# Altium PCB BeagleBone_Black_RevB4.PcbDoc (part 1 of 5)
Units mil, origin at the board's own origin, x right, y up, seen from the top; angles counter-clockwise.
Board outline 3401 x 2151 mil, 6 copper layers (TOP, LYR2_GND, LYR3, LYR4, LYR5_PWR, BOTTOM), stack 62 mil thick; 381 components, 310 nets, 1705 pads, 850 vias.
Unrouted connection lines stored in the file: 1.
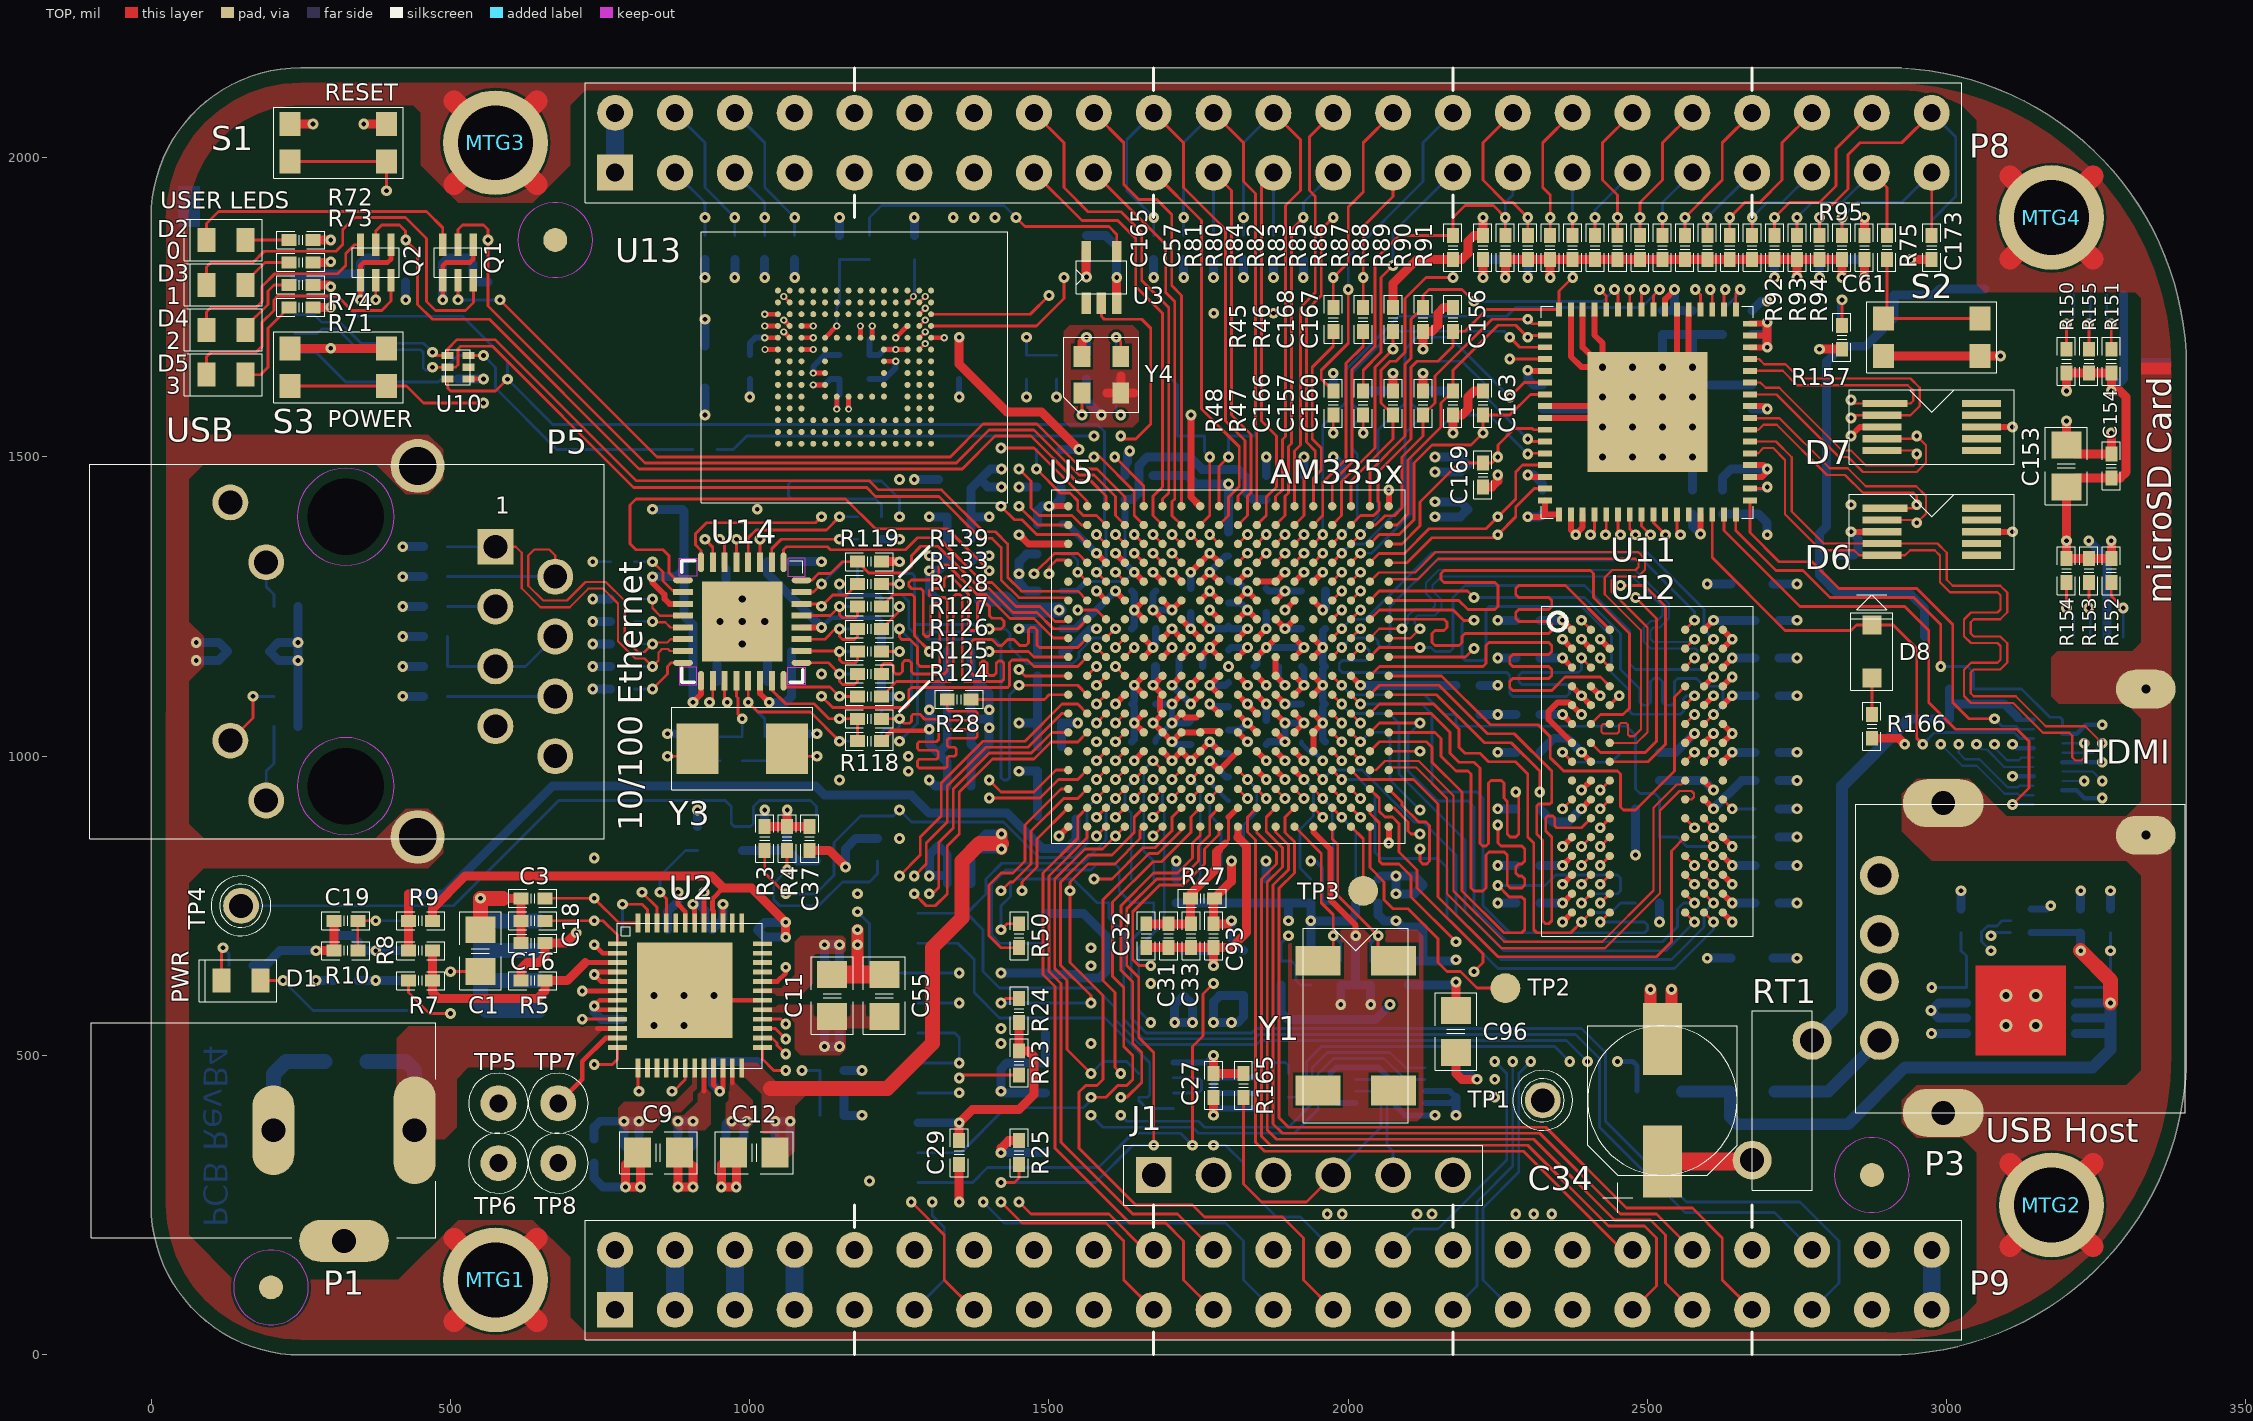
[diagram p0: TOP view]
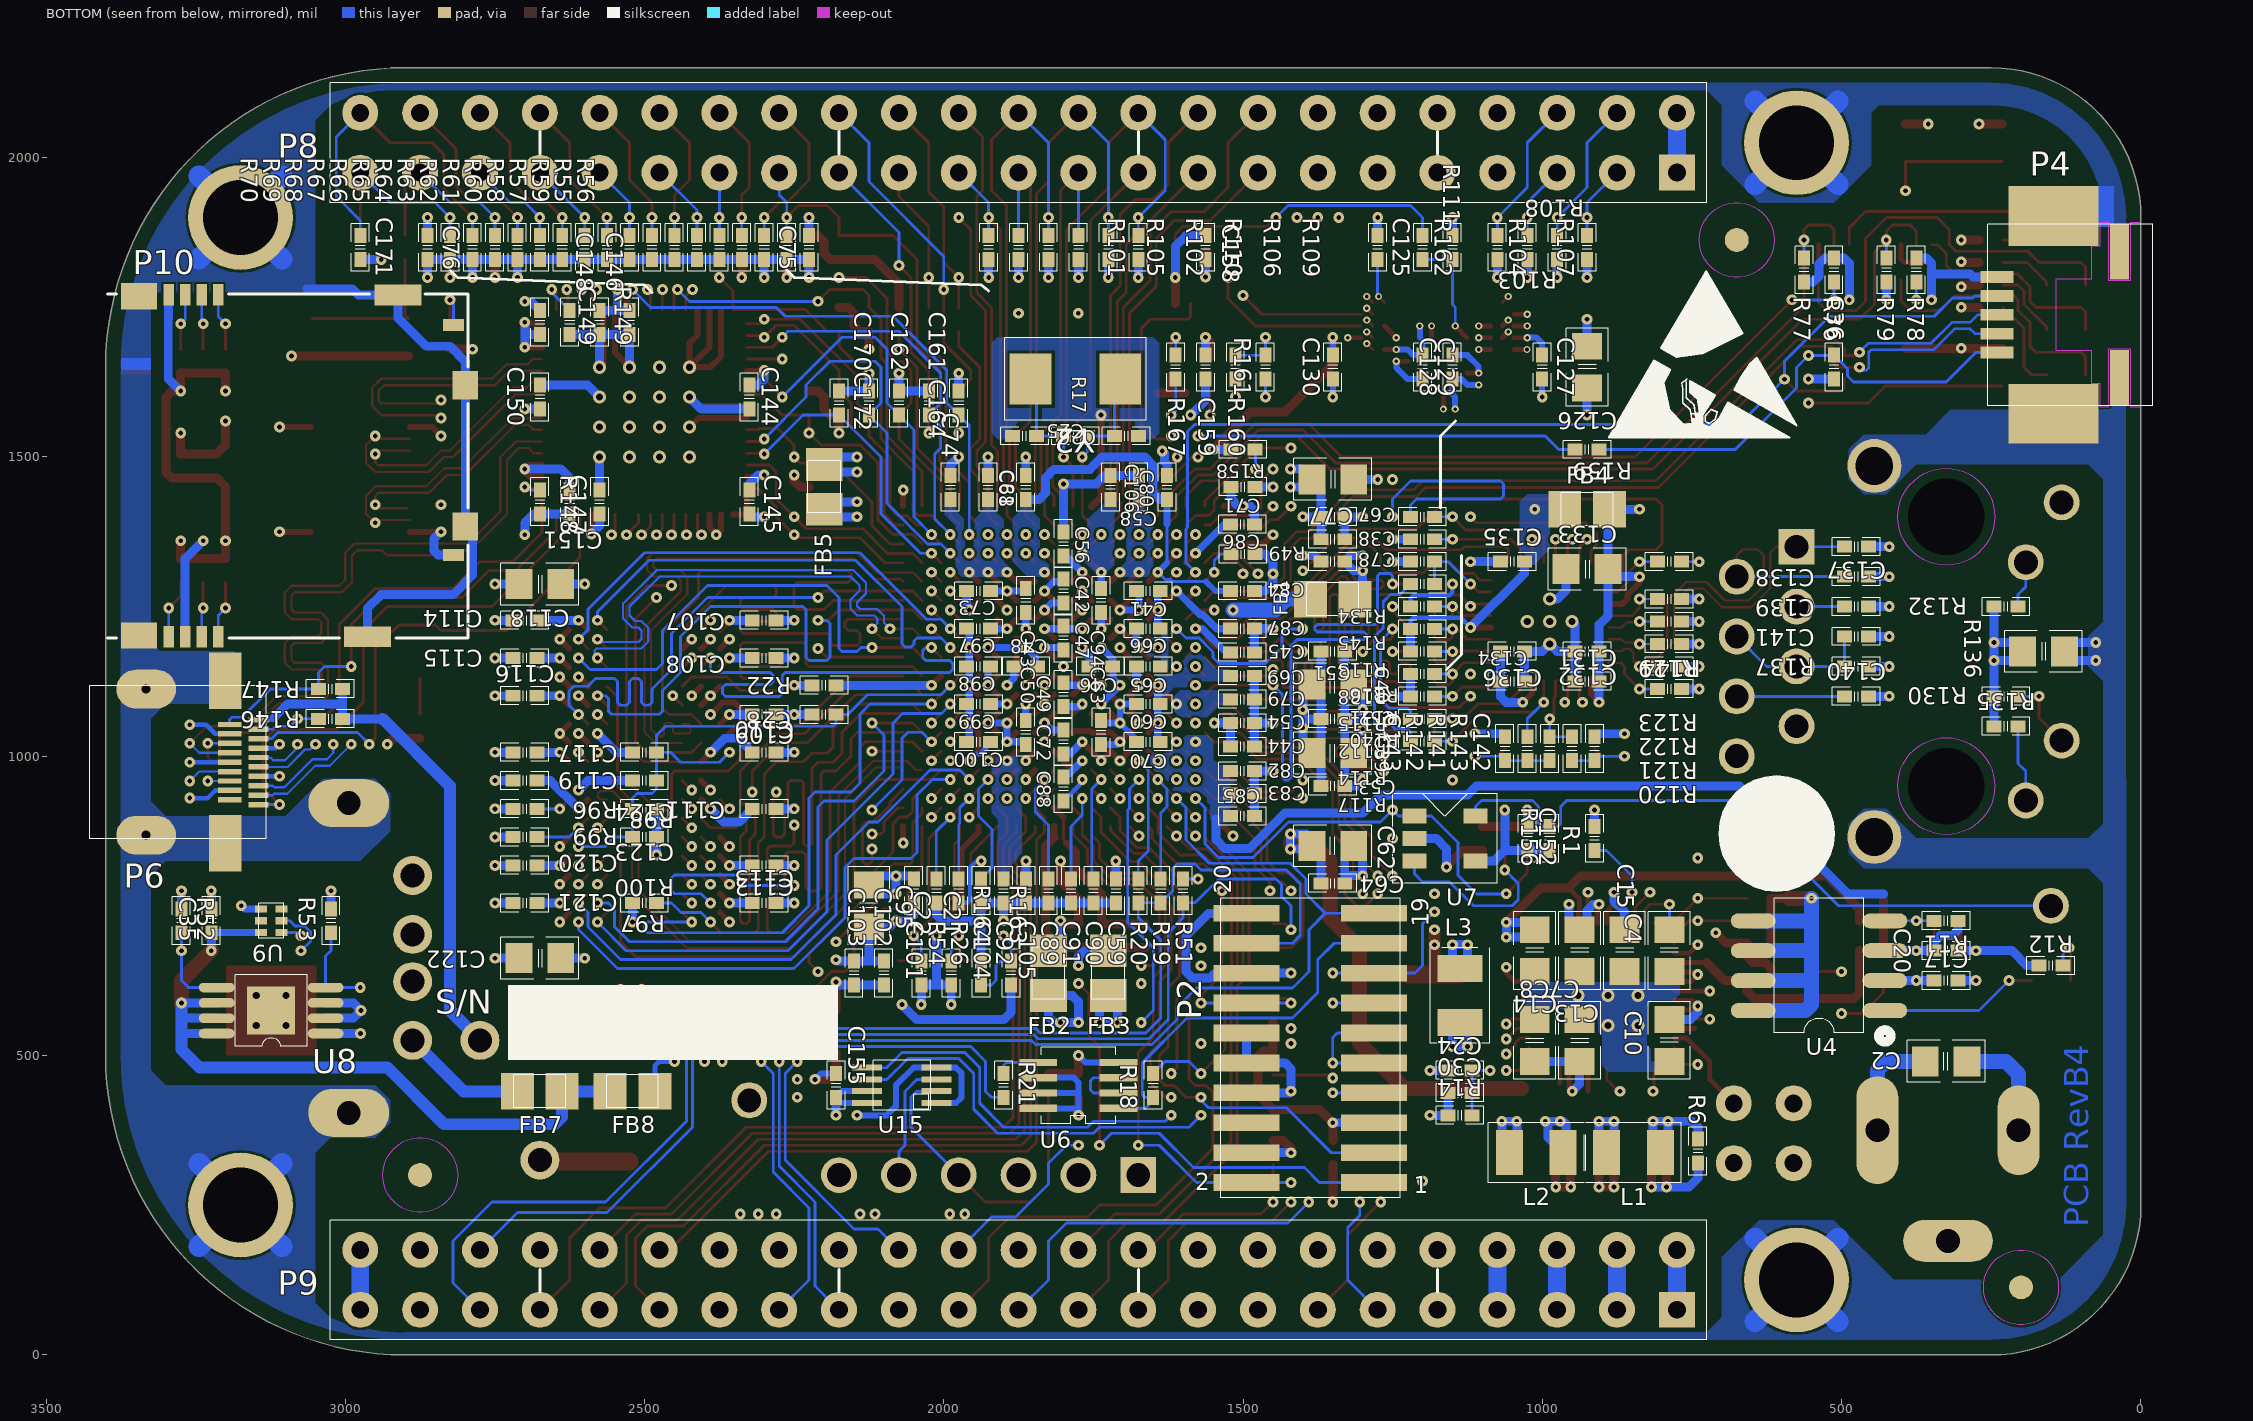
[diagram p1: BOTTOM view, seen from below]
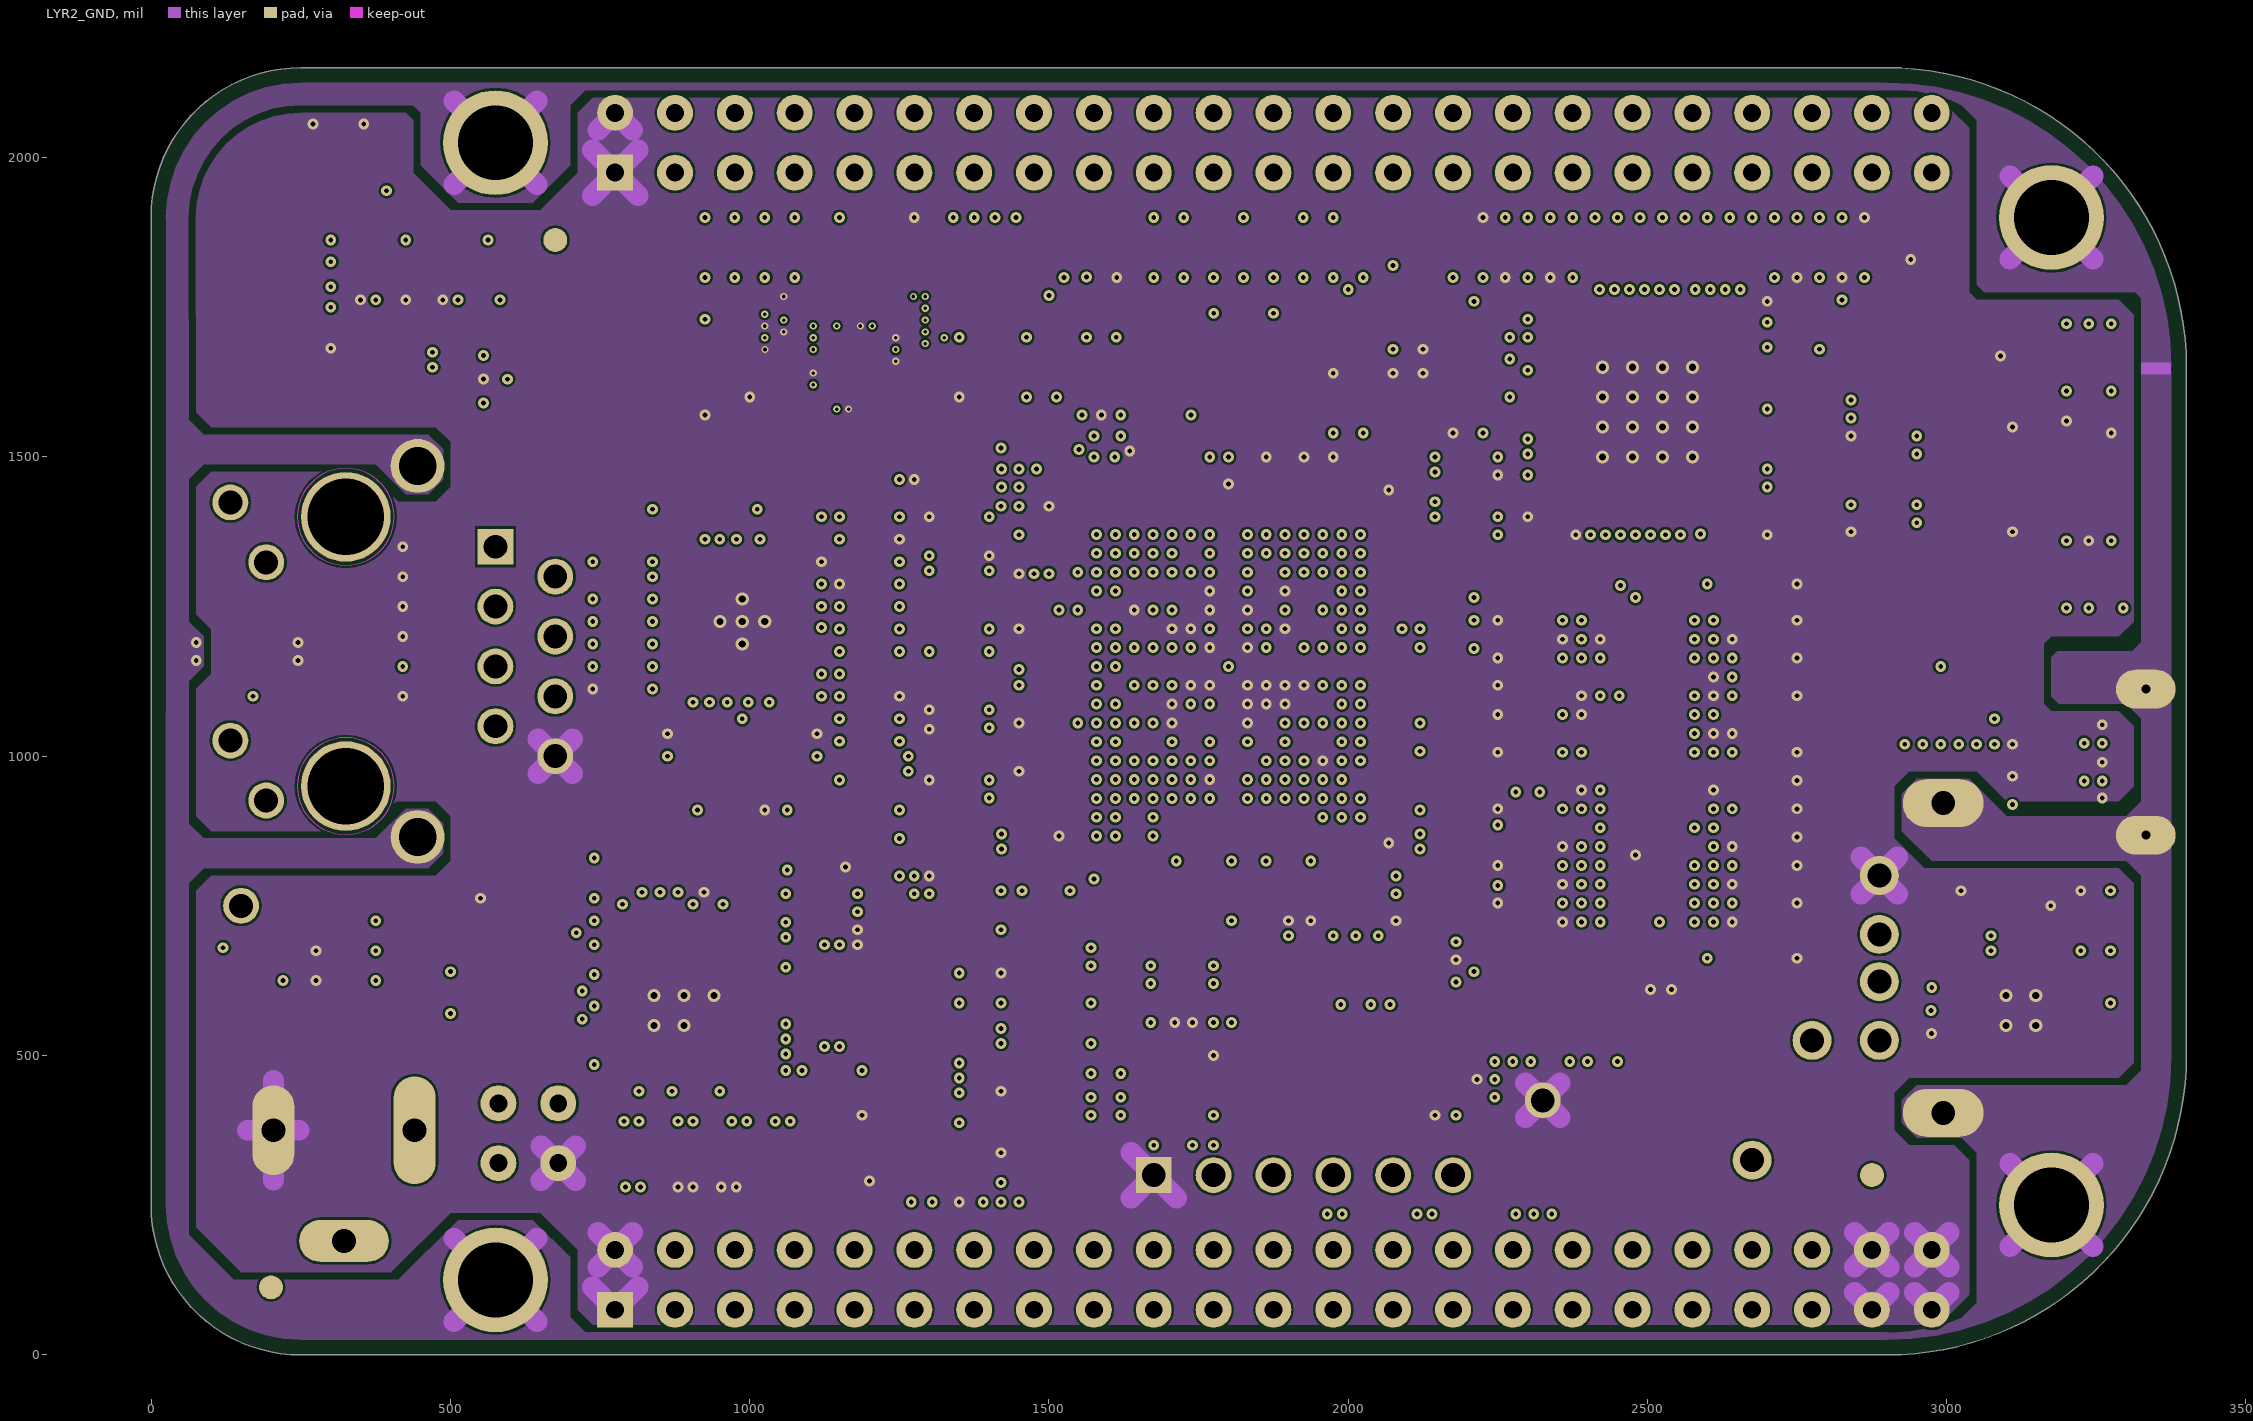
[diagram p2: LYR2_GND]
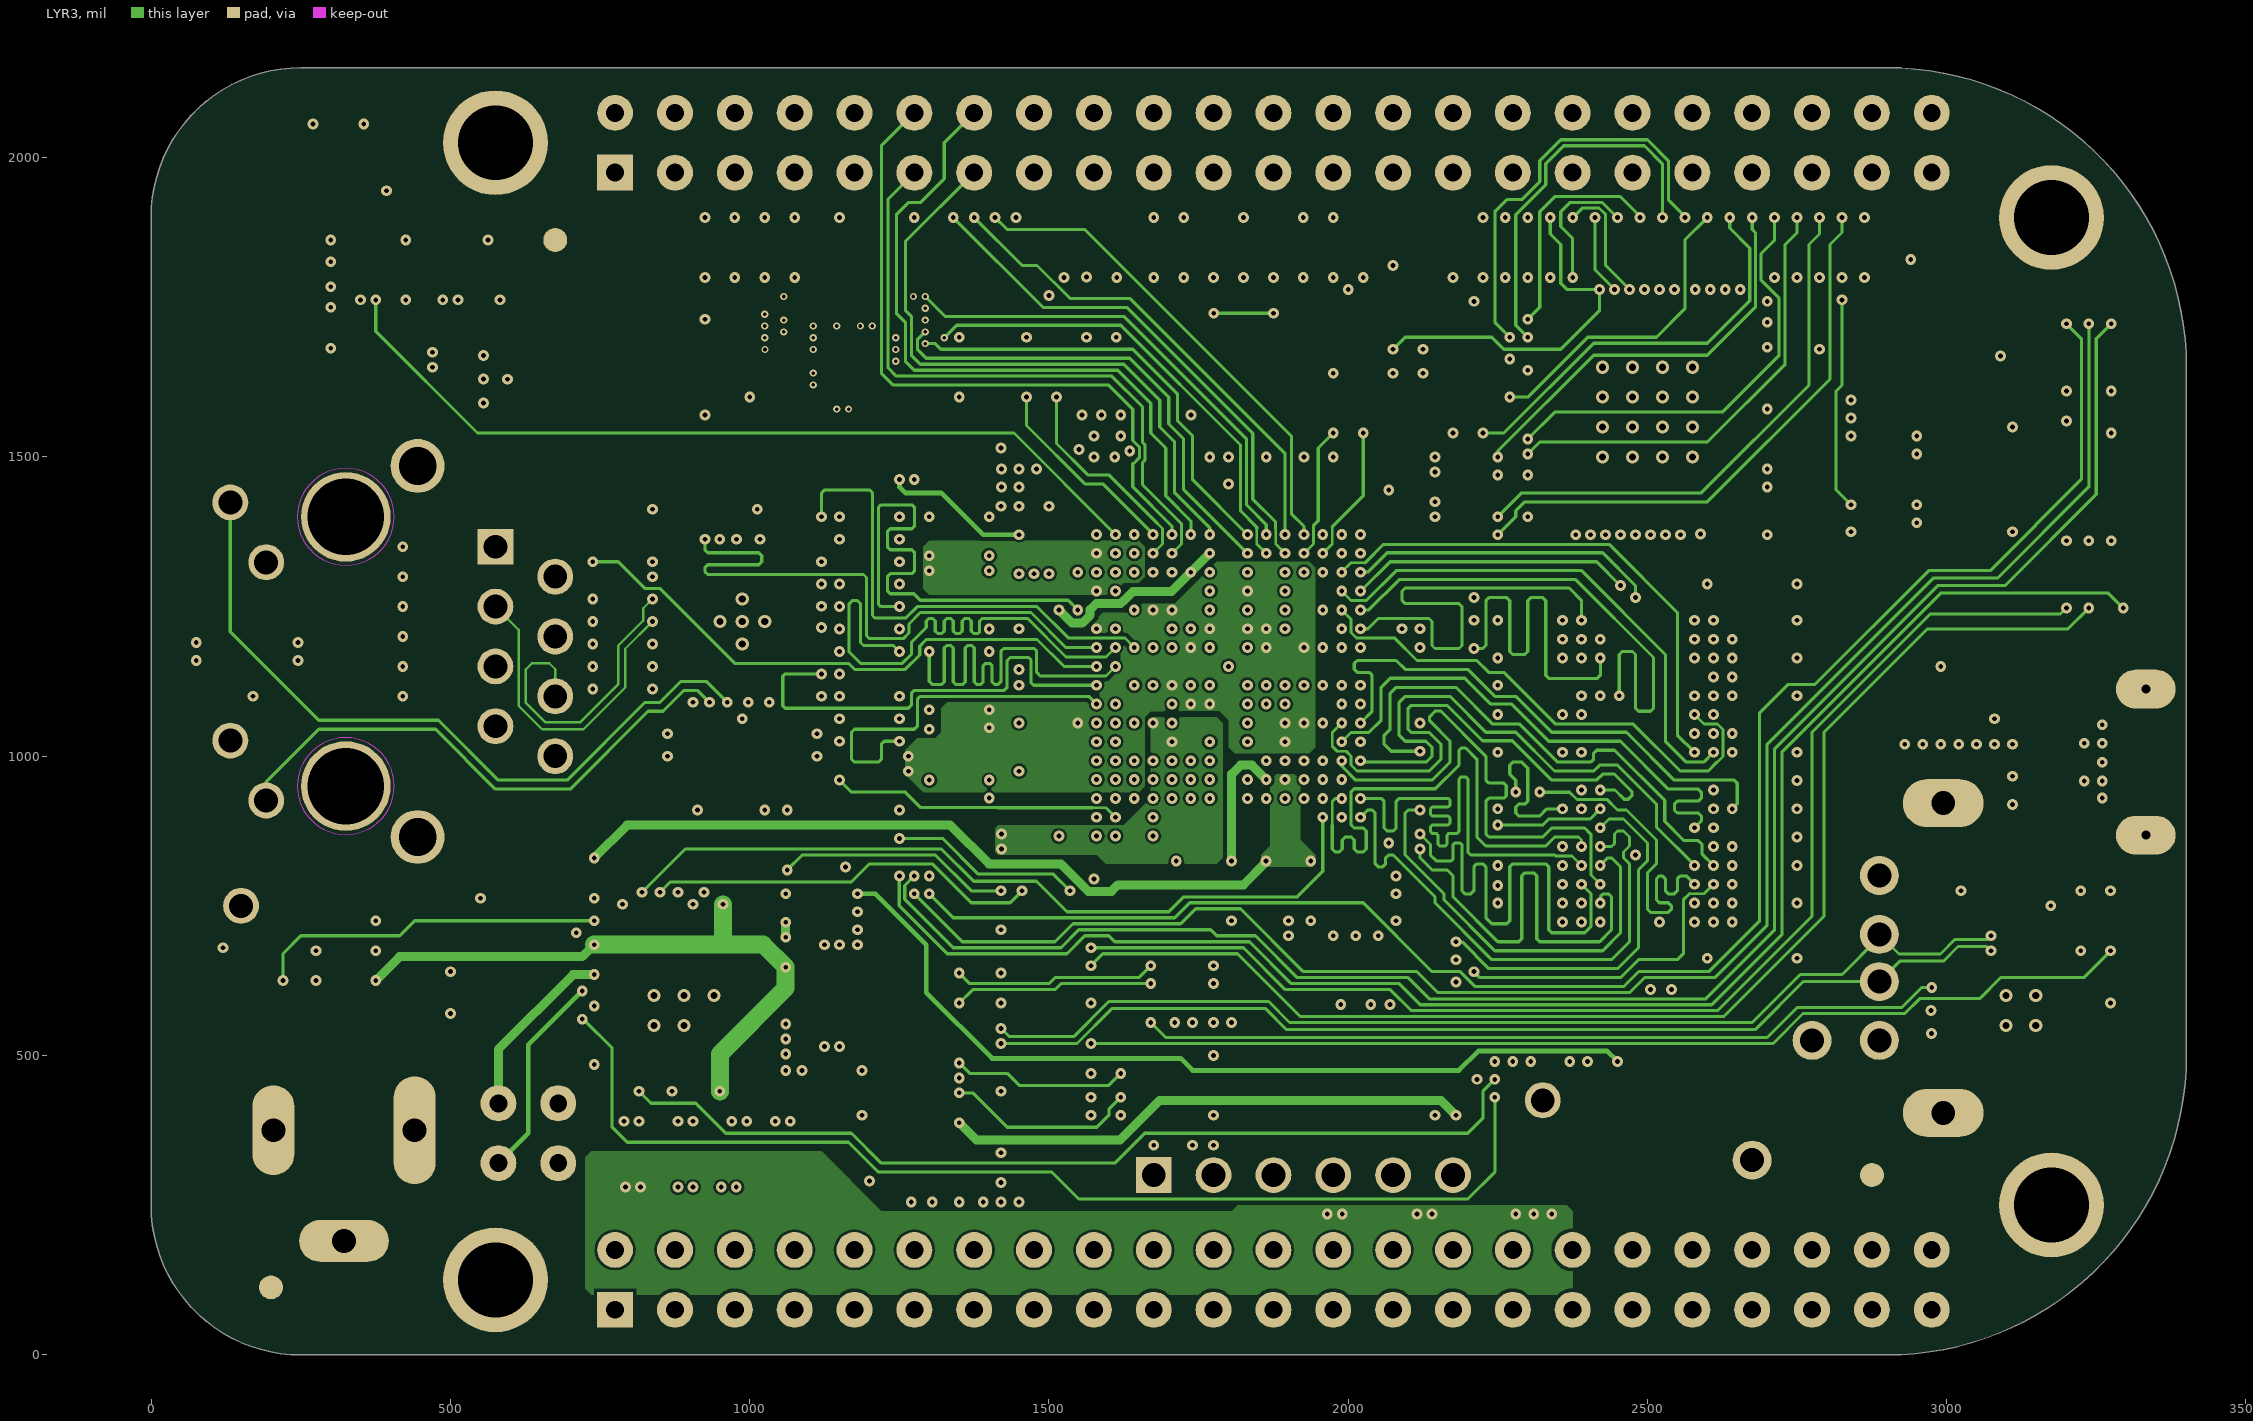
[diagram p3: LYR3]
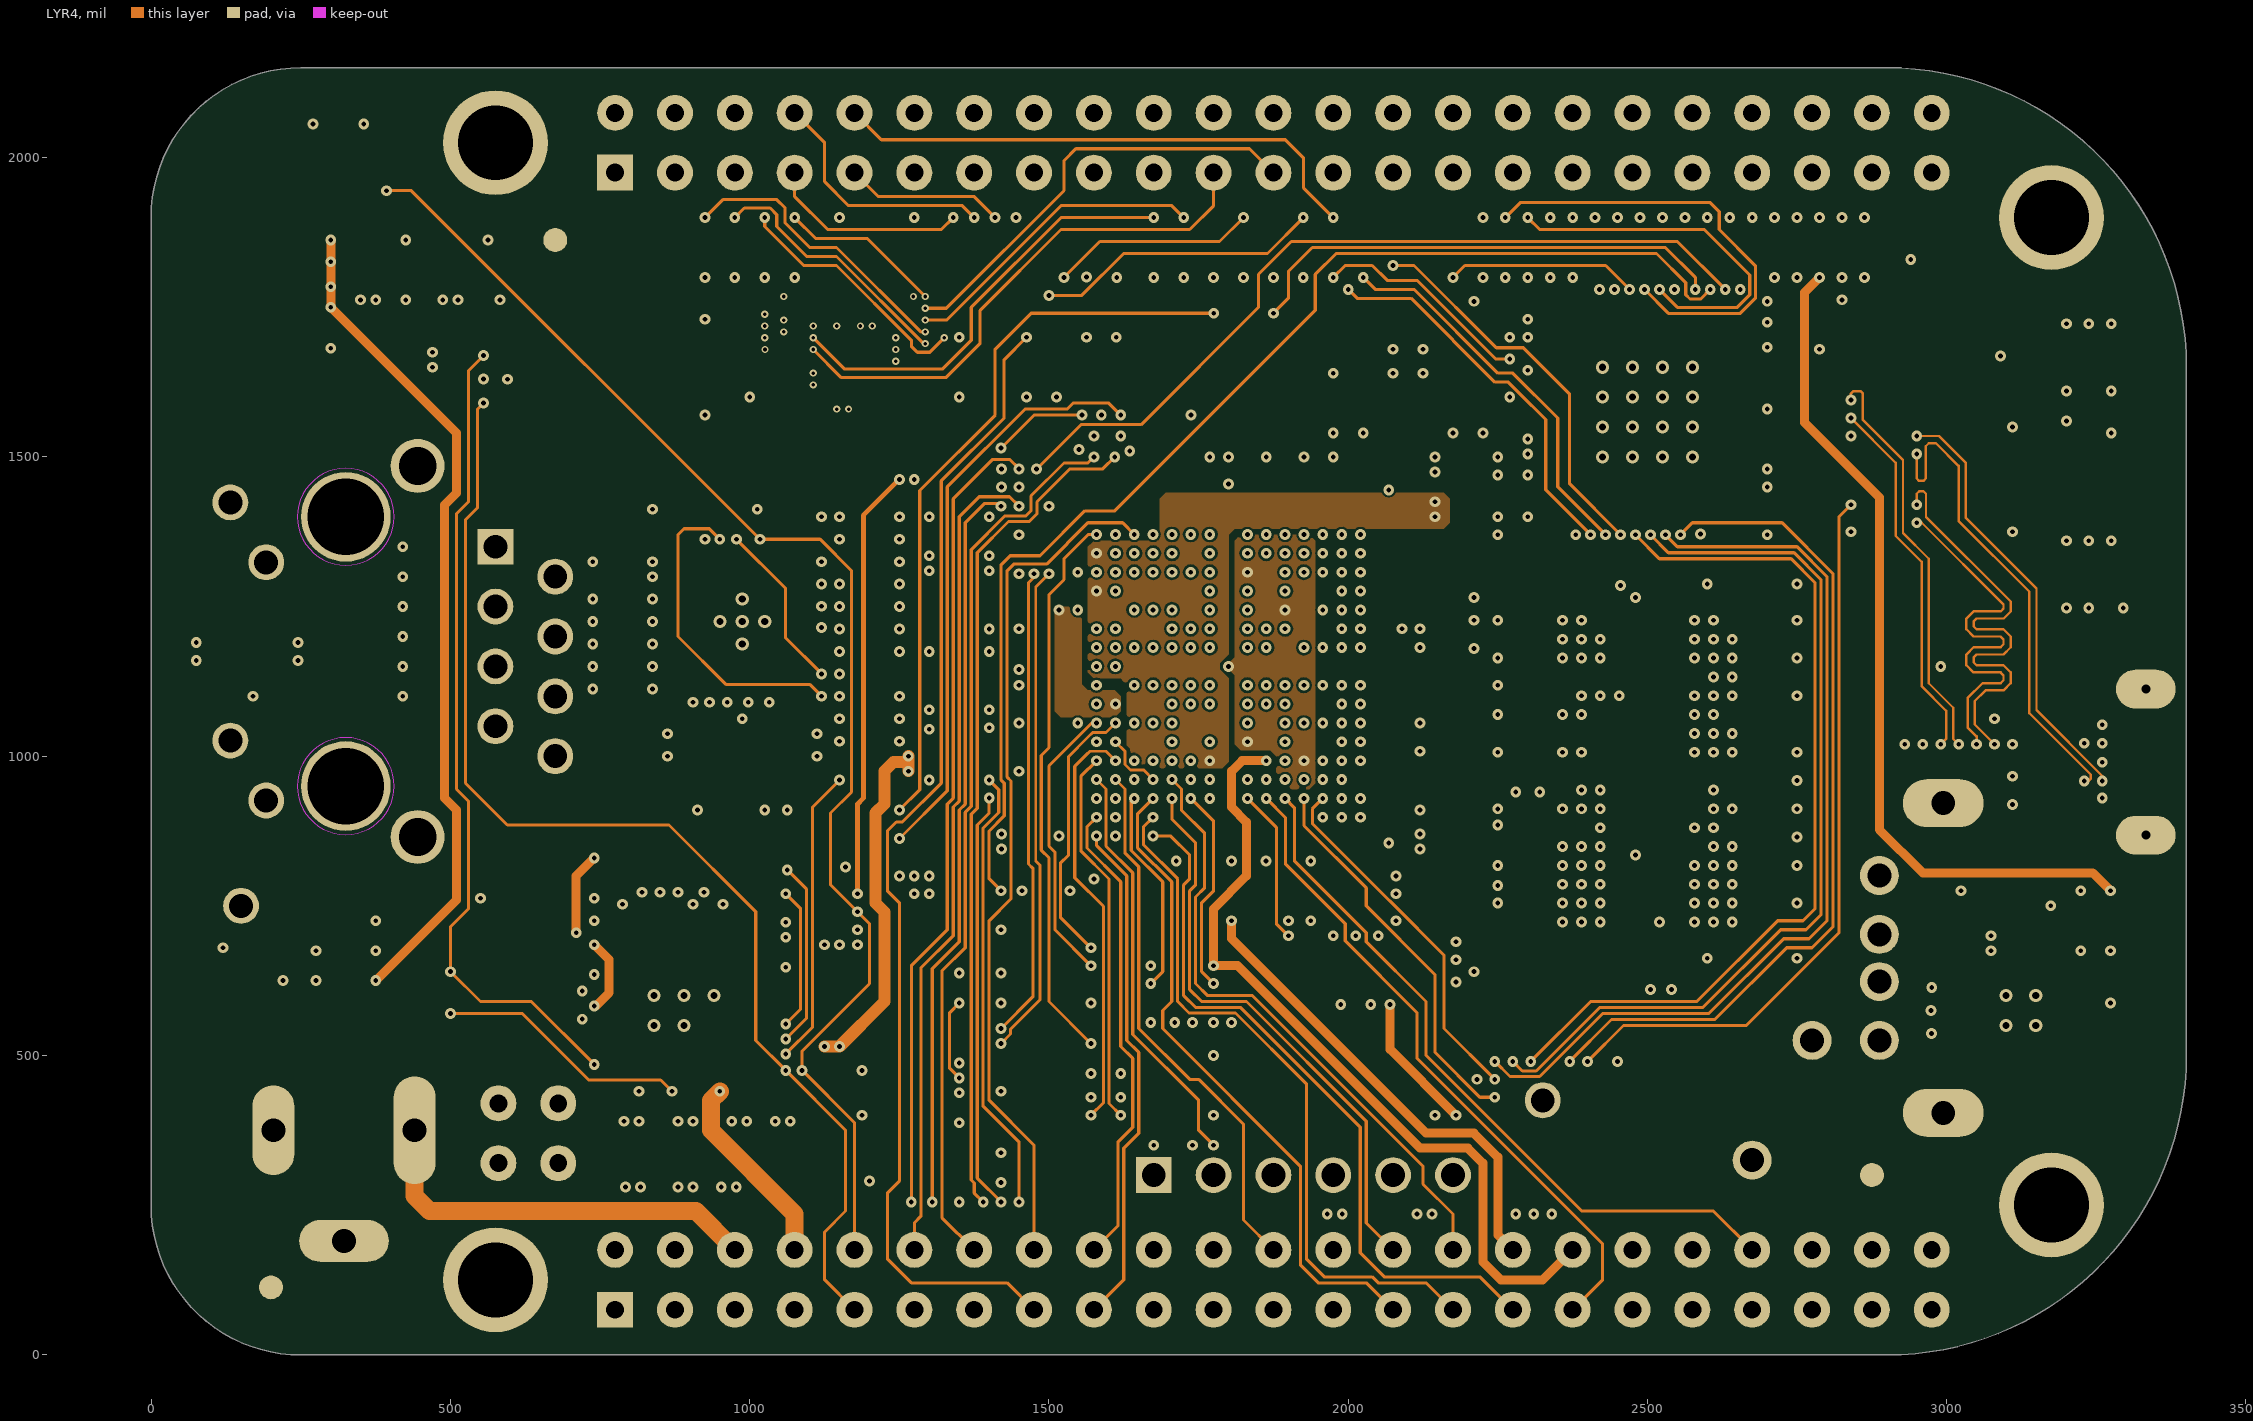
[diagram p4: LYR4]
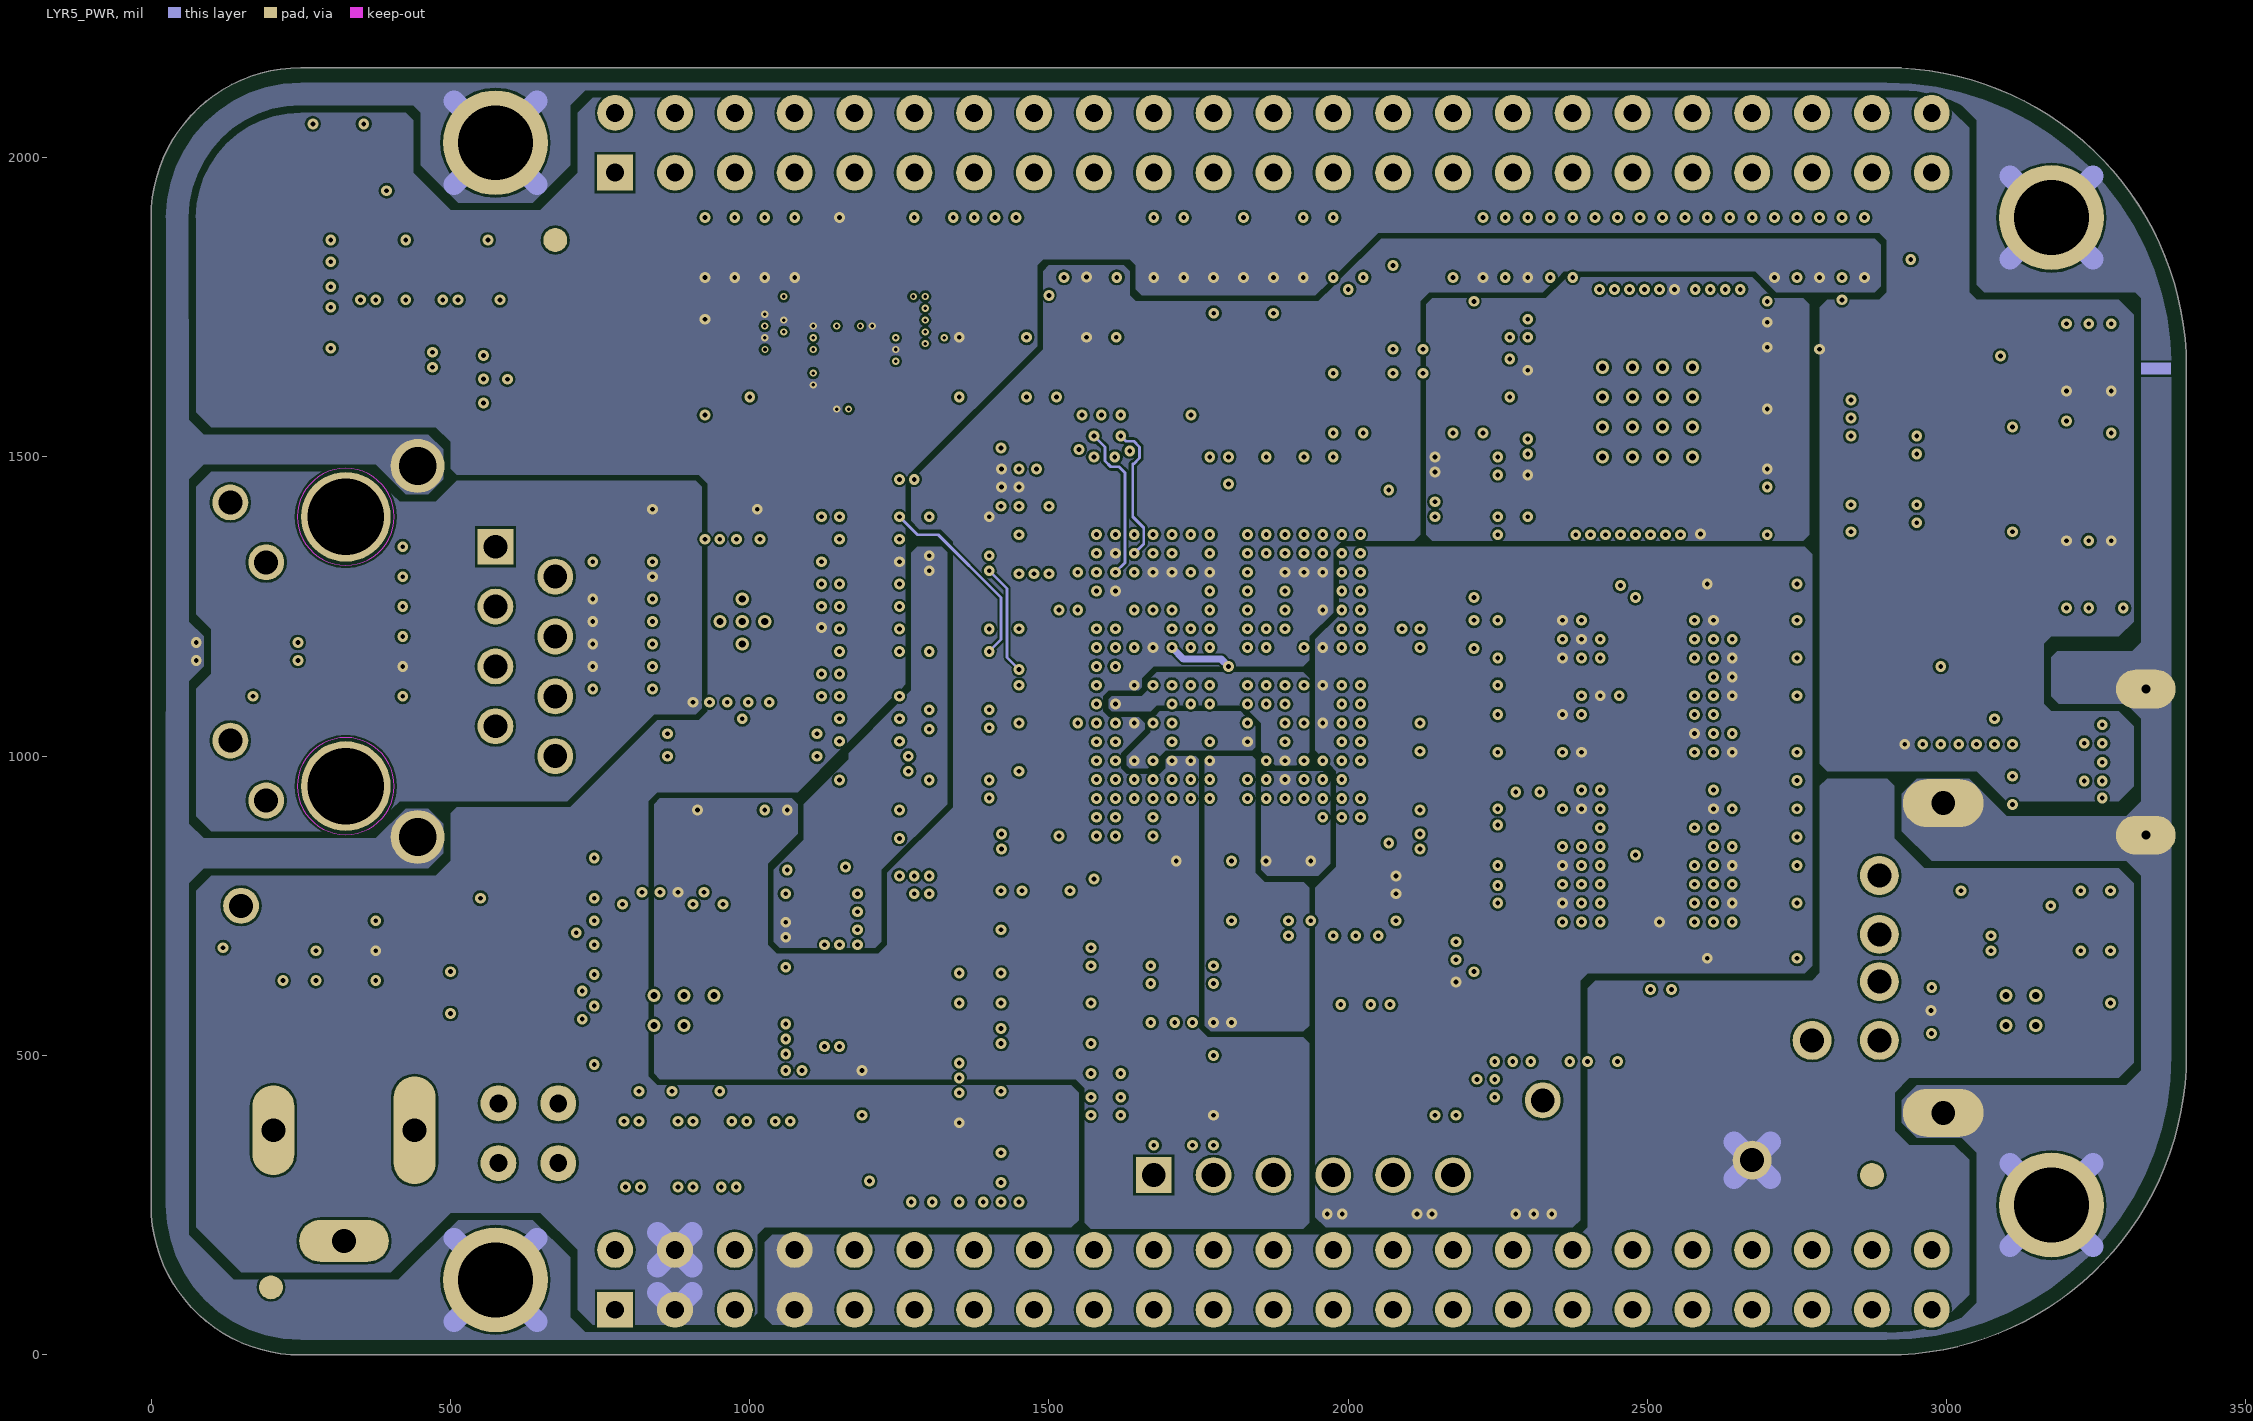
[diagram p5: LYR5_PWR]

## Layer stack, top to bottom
TOP: signal copper 2.4
Dielectric: core 3.6, FR-4, Dk 4.05
LYR2_GND: signal copper 1.2
Dielectric: core 4.6, FR-4, Dk 4.5
LYR3: signal copper 1.2
Dielectric: core 36, FR-4, Dk 4.5
LYR4: signal copper 1.2
Dielectric: core 4.6, FR-4, Dk 4.5
LYR5_PWR: signal copper 1.2
Dielectric: core 3.6, FR-4, Dk 4.05
BOTTOM: signal copper 2.4

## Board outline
-0.5,250 ccw(c250,250) 250,-0.5 2900,-0.5 ccw(c2900,500) 3400.5,500 3400.5,1650 ccw(c2900,1650) 2900,2150.5 250,2150.5 ccw(c250,1900) -0.5,1900

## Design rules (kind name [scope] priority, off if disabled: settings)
Clearance [All] p1: gap=4
PlaneConnect [All] p1: planeconnectstyle=Direct reliefexpansion=20 reliefentries=4 reliefconductorwidth=10 reliefairgap=10
PolygonConnect [All] p1: connectstyle=Direct reliefconductorwidth=10 reliefentries=4 polygonreliefangle="90 Angle" airgapwidth=10
RoomDefinition CompsKeepOut3 [All vs False] p1: confinementstyle=ConfineOut formatcopy=TRUE lockcomponents=FALSE outline 725.46,2025 723.61,2048.54 718.1,2071.5 709.06,2093.31 696.73,2113.44 681.39,2131.39 663.44,2146.73 643.31,2159.06 621.5,2168.1 598.54,2173.61 575,2175.46 551.46,2173.61 528.5,2168.1 506.69,2159.06 486.56,2146.73 468.61,2131.39 453.27,2113.44 440.94,2093.31 431.9,2071.5 426.39,2048.54 424.54,2025 426.39,2001.46 431.9,1978.5 440.94,1956.69 453.27,1936.56 468.61,1918.61 486.56,1903.27 506.69,1890.94 528.5,1881.9 551.46,1876.39 575,1874.54 598.54,1876.39 621.5,1881.9 643.31,1890.94 663.44,1903.27 681.39,1918.61 696.73,1936.56 709.06,1956.69 718.1,1978.5 723.61,2001.46 725.46,2025
RoomDefinition CompsKeepOut2 [All vs False] p2: confinementstyle=ConfineOut formatcopy=TRUE lockcomponents=FALSE outline 3325,1900 3324.43,1913.07 3322.72,1926.05 3319.89,1938.82 3315.95,1951.3 3310.95,1963.39 3304.9,1975 3297.87,1986.04 3289.91,1996.42 3281.07,2006.07 3271.42,2014.91 3261.04,2022.87 3250,2029.9 3238.39,2035.95 3226.3,2040.95 3213.82,2044.89 3201.05,2047.72 3188.07,2049.43 3175,2050 3161.93,2049.43 3148.95,2047.72 3136.18,2044.89 3123.7,2040.95 3111.61,2035.95 3100,2029.9 3088.96,2022.87 3078.58,2014.91 3068.93,2006.07 3060.09,1996.42 3052.13,1986.04 3045.1,1975 3039.05,1963.39 3034.05,1951.3 3030.11,1938.82 3027.28,1926.05 3025.57,1913.07 3025,1900 3025.57,1886.93 3025.85,1884 3034,1884 3034,1848.82 3039,1836.73 3045.03,1825.11 3052.05,1814.07 3060.01,1803.68 3068.84,1794.03 3078.48,1785.18 3088.86,1777.2 3099.89,1770.16 3111.49,1764.11 3123.57,1759.09 3136.05,1755.15 3148.82,1752.3 3161.8,1750.58 3174.87,1750 3187.94,1750.56 3200.92,1752.26 3213.7,1755.08 3226.18,1759 3238.27,1764 3249.89,1770.03 3260.93,1777.05 3271.32,1785.01 3280.97,1793.84 3289.82,1803.48 3297.8,1813.86 3304.84,1824.89 3310.89,1836.49 3315.91,1848.57 3319.85,1861.05 3322.7,1873.82 3324.42,1886.8 3325,1899.87 3325,1900
RoomDefinition CompsKeepOut1 [All vs False] p3: confinementstyle=ConfineOut formatcopy=TRUE lockcomponents=FALSE outline 3325,250 3324.43,263.07 3322.72,276.05 3319.89,288.82 3315.95,301.3 3310.95,313.39 3304.9,325 3297.87,336.04 3289.91,346.42 3281.07,356.07 3271.42,364.91 3261.04,372.87 3250,379.9 3238.39,385.95 3234.67,387.62 3115.33,387.62 3103.56,381.9 3092.34,375.17 3081.74,367.49 3071.86,358.91 3062.76,349.51 3054.51,339.35 3047.18,328.51 3040.83,317.07 3035.49,305.12 3034.15,301.6 3034.15,241.25 3034.15,241.01 3033.79,240.65 3033.61,240.65 3033.6,240.64 3033.54,240.64 3031.78,238.88 3025.41,238.88 3026.95,225.89 3029.62,213.07 3033.39,200.54 3038.24,188.39 3044.13,176.7 3051.02,165.58 3058.85,155.09 3067.56,145.33 3077.1,136.37 3087.37,128.27 3098.32,121.09 3109.85,114.9 3121.87,109.73 3134.3,105.64 3147.03,102.64 3159.99,100.76 3173.05,100.02 3186.13,100.42 3199.12,101.96 3211.94,104.63 3224.47,108.4 3236.62,113.25 3248.31,119.14 3259.43,126.03 3269.92,133.86 3279.68,142.57 3288.64,152.11 3296.74,162.38 3303.92,173.33 3310.11,184.86 3315.28,196.88 3319.37,209.31 3322.37,222.04 3324.25,235 3324.99,248.06 3325,250
RoomDefinition CompsKeepOut0 [All vs False] p4: confinementstyle=ConfineOut formatcopy=TRUE lockcomponents=FALSE outline 725,125 724.43,138.07 722.72,151.05 719.89,163.82 715.95,176.3 710.95,188.39 704.9,200 697.87,211.04 689.91,221.42 681.07,231.07 671.42,239.91 661.04,247.87 650,254.9 638.39,260.95 626.3,265.95 613.82,269.89 601.05,272.72 588.07,274.43 575,275 561.93,274.43 548.95,272.72 536.18,269.89 523.7,265.95 511.61,260.95 500,254.9 488.96,247.87 485.03,245.02 485.03,194.57 475.08,184.62 437.36,184.62 432.69,172.4 429.1,159.81 426.62,146.97 425.27,133.95 425.06,120.86 425.99,107.81 428.05,94.89 431.24,82.2 435.51,69.83 440.85,57.88 447.21,46.45 454.55,35.61 462.8,25.45 471.9,16.05 481.79,7.48 492.38,-0.2 503.61,-6.92 515.38,-12.64 527.6,-17.31 540.19,-20.9 553.03,-23.38 566.05,-24.73 579.14,-24.94 592.19,-24.01 605.11,-21.95 617.8,-18.76 630.17,-14.49 642.12,-9.15 653.55,-2.79 664.39,4.55 674.55,12.8 683.95,21.9 692.52,31.79 700.2,42.38 706.92,53.61 712.64,65.38 717.31,77.6 720.9,90.19 723.38,103.03 724.73,116.05 725,125
RoutingVias [All] p1: holewidth=28 width=50 viastyle="Through Hole" minholewidth=28 minwidth=50 maxholewidth=28 maxwidth=50
SolderMaskExpansion [All] p1: expansion=4
Width [All] p1: maxlimit=10 minlimit=10 preferedwidth=10 impedancedriven=TRUE minimp=0.000000 maximp=0.000000 favimp=0.000000
27 further rules are at their usual default settings.

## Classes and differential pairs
net class DDR_BA[2..0]: DDR_BA0 DDR_BA1 DDR_BA2
net class DDR_A[15..0]: DDR_A0 DDR_A1 DDR_A2 DDR_A3 DDR_A4 DDR_A5 DDR_A6 DDR_A7 DDR_A8 DDR_A9 DDR_A10 DDR_A11 DDR_A12 DDR_A13 DDR_A14 DDR_A15
component class "P11_Exp Conn, uSD, and ": C152 C153 C154 P8 P9 P10 R150 R151 R152 R153 R154 R155 R156 R157 TP4 U7
component class "P10_HDMI Framer": C144 C145 C146 C147 C148 C149 C150 C151 C156 C157 C160 C161 C162 C163 C164 C165 C166 C167 C168 C169 C170 C171 C172 C173 D6 D7 D8 FB5 P6 R146 R147 R148 R149 R158 R166 RT1 U11
component class P09_Ethernet: C131 C132 C133 C134 C135 C136 C137 C138 C139 C140 C141 C142 C143 FB4 P5 R112 R113 R114 R115 R116 R117 R118 R119 R120 R121 R122 R123 R124 R125 R126 R127 R128 R129 R130 R131 R132 R133 R134 R135 R136 R137 R138 R139 R140 R141 R142 R143 R144 R145 U14 Y3
component class P08_eMMC: C125 C126 C127 C128 C129 C130 R101 R102 R103 R104 R105 R106 R107 R108 R109 R110 R111 U13
component class "P07_DDR3 Memory": C107 C108 C109 C110 C111 C112 C113 C114 C115 C116 C117 C118 C119 C120 C121 C122 C123 C124 R96 R97 R98 R99 R100 U12
component class "P06_LED, Config, & Button": D2 D3 D4 D5 Q1 Q2 R55 R56 R57 R58 R59 R60 R61 R62 R63 R64 R65 R66 R67 R68 R69 R70 R71 R72 R73 R74 R75 R76 R77 R78 R79 R80 R81 R82 R83 R84 R85 R86 R87 R88 R89 R90 R91 R92 R93 R94 R95 S2
component class "P05_Processor Page 3 of 3": C37 C38 C39 C40 C41 C42 C43 C44 C45 C46 C47 C48 C49 C50 C51 C52 C53 C54 C55 C56 C57 C58 C59 C60 C61 C62 C63 C64 C65 C66 C67 C68 C69 C70 C71 C72 C73 C74 C75 C76 C77 C78 C79 C80 C81 C82 C83 C84 C85 C86 C87 C88 C89 C90 C91 C92 C93 C94 C95 C96 C97 C98 C99 C100 C101 C102 C103 C104 C105 C106 FB1 FB2 FB3 R54 TP2 TP3
component class "P04_Processor 2 or 3, USB and Serial": C31 C32 C33 C34 C35 C36 C155 FB7 FB8 J1 P3 P4 R26 R27 R28 R45 R46 R47 R48 R49 R50 R51 R52 R53 R159 R163 R164 R165 U8 U9 U10 U15
component class "P03_Processor 1 of 3, JTAG Header": C21 C22 C24 C25 C26 C27 C28 C29 C30 C158 C159 P2 R14 R17 R18 R19 R20 R21 R22 R23 R24 R25 R160 R161 R162 R167 S1 U3 U5 U6 Y1 Y2 Y4
component class "P02_Power Management": C1 C2 C3 C4 C7 C8 C9 C10 C11 C12 C13 C14 C15 C16 C17 C18 C19 C20 D1 L1 L2 L3 MTG1 MTG2 MTG3 MTG4 P1 R1 R3 R4 R5 R6 R7 R8 R9 R10 R11 R12 S3 TP1 TP5 TP6 TP7 TP8 U2 U4
net class DDR_D[15..0]: DDR_D0 DDR_D1 DDR_D2 DDR_D3 DDR_D4 DDR_D5 DDR_D6 DDR_D7 DDR_D8 DDR_D9 DDR_D10 DDR_D11 DDR_D12 DDR_D13 DDR_D14 DDR_D15

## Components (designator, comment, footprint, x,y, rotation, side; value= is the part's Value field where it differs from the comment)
C1 "10uF, 10V" 805 550,675 r270 top
C2 "10uF, 10V" 805 325,490 r0 bottom
C3 "0.1uf, 6V3" 402 637.5,762.5 r0 top
C4 "10uF, 10V" 805 787.5,675 r90 bottom
C7 "10uF, 10V" 805 937.5,525 r270 bottom
C8 "10uF, 10V" 805 1012.5,525 r270 bottom
C9 "10uF, 10V" 805 847.5,337.5 r180 top
C10 "10uF, 10V" 805 787.5,525 r90 bottom
C11 "10uF, 10V" 805 1137.5,600 r270 top
C12 "10uF, 10V" 805 1007.5,337.5 r0 top
C13 "10uF, 10V" 805 937.5,675 r90 bottom
C14 "10uF, 10V" 805 1012.5,675 r90 bottom
C15 "10uF, 10V" 805 862.5,675 r90 bottom
C16 "2.2uF, 6V3" 402 637.5,687.5 r180 top
C17 "2.2uF, 6V3" 402 325,625 r180 bottom
C18 "2.2uF, 6V3" 402 637.5,725 r180 top
C19 "470pF, 50V" 402 325,725 r180 top
C20 "0.1uf, 6V3" 402 325,675 r180 bottom
C21 "18pF, 50V" 402 1987.5,637.5 r90 bottom
C22 "18pF, 50V" 402 2037.5,637.5 r90 bottom
C24 "1uF, 10V" 402 1137.5,437.5 r0 bottom
C25 "18pF, 50V" 402 1865,1535 r0 bottom
C26 "18pF, 50V" 402 1695,1535 r180 bottom
C27 "0.1uf, 6V3" 402 1775,450 r90 top
C28 "0.1uf, 6V3" 402 2200,1069.5 r0 bottom
C29 "0.1uf, 6V3" 402 1350,337.5 r270 top
C30 "0.1uf, 6V3" 402 1137.5,400 r0 bottom
C31 "0.1uf, 6V3" 402 1700,700 r270 top
C32 "1nF, 50V" 402 1662.5,700 r270 top
C33 "0.1uf, 6V3" 402 1737.5,700 r270 top
C34 "100uF, 6V3" RD205SMD_250D 2525,425 r90 top
C35 "0.1uf, 6V3" 402 3223.9,725 r90 bottom
C36 "0.1uf, 6V3" 402 512.5,1650 r270 bottom
C37 "0.1uf, 6V3" 402 1100,862.5 r270 top
C38 "0.1uf, 6V3" 402 1350,1362.5 r180 bottom
C39 "10uF, 10V" 805 1350,1005 r0 bottom
C40 "10uF, 10V" 805 1350,1120 r0 bottom
C41 "0.1uf, 6V3" 402 1658.25,1276 r180 bottom
C42 "0.1uf, 6V3" 402 1800,1275.76 r270 bottom
C43 "0.1uf, 6V3" 402 1863,1260.25 r90 bottom
C44 "0.1uf, 6V3" 402 1500.75,1016.13 r180 bottom
C45 "0.1uf, 6V3" 402 1500.75,1173.63 r180 bottom
C46 "0.1uf, 6V3" 402 1737.7,1150 r0 bottom
C47 "0.1uf, 6V3" 402 1800,1197.25 r270 bottom
C48 "0.1uf, 6V3" 402 1863,1150 r0 bottom
C49 "0.1uf, 6V3" 402 1800,1102.75 r90 bottom
C50 "0.1uf, 6V3" 402 1863,1039.75 r90 bottom
C51 "0.1uf, 6V3" 402 1350,1175 r180 bottom
C52 "0.1uf, 6V3" 402 1350,1062.5 r180 bottom
C53 "0.1uf, 6V3" 402 1350,950 r180 bottom
C54 "0.1uf, 6V3" 402 1500.75,1055.5 r180 bottom
C55 "10uF, 10V" 805 1225,600 r270 top
C56 "0.1uf, 6V3" 402 1800,1354.75 r270 bottom
C57 "0.1uf, 6V3" 402 2225,1850 r270 top
C58 "0.1uf, 6V3" 402 1674,1449.25 r90 bottom
C59 "0.1uf, 6V3" 402 1712.5,775 r270 bottom
C60 "0.1uf, 6V3" 402 1658.25,1087 r180 bottom
C61 "0.1uf, 6V3" 402 2862.5,1850 r270 top
C62 "10uF, 10V" 805 1350,850 r0 bottom
C63 "0.1uf, 6V3" 402 1737,1039.75 r90 bottom
C64 "0.1uf, 6V3" 402 1350,787.5 r180 bottom
C65 "0.1uf, 6V3" 402 1658.25,1150 r180 bottom
C66 "0.1uf, 6V3" 402 1658.25,1213 r180 bottom
C67 "0.1uf, 6V3" 402 1350,1400 r180 bottom
C68 "0.1uf, 6V3" 402 1926,1449.25 r270 bottom
C69 "0.1uf, 6V3" 402 1500.75,1134.25 r0 bottom
C70 "0.1uf, 6V3" 402 1658.25,1024 r180 bottom
C71 "0.1uf, 6V3" 402 1500,1450 r180 bottom
C72 "0.1uf, 6V3" 402 1800,1023.98 r270 bottom
C73 "0.1uf, 6V3" 402 1941.75,1276 r0 bottom
C74 "0.1uf, 6V3" 402 1989,1449.25 r270 bottom
C75 "0.1uf, 6V3" 402 2225,1850 r270 bottom
C76 "0.1uf, 6V3" 402 2862.5,1850 r270 bottom
C77 "10uF, 10V" 805 1350,1462.5 r180 bottom
C78 "0.1uf, 6V3" 402 1350,1325 r0 bottom
C79 "0.1uf, 6V3" 402 1500.75,1094.88 r180 bottom
C80 "0.1uf, 6V3" 402 1626.77,1449.25 r90 bottom
C81 "0.1uf, 6V3" 402 1863,1449.25 r90 bottom
C82 "0.1uf, 6V3" 402 1500.75,975 r180 bottom
C83 "0.1uf, 6V3" 402 1500.75,937.38 r180 bottom
C84 "0.1uf, 6V3" 402 1500.75,1276 r180 bottom
C85 "0.1uf, 6V3" 402 1500.75,900 r180 bottom
C86 "0.1uf, 6V3" 402 1500.75,1387.5 r180 bottom
C87 "0.1uf, 6V3" 402 1500.75,1213 r180 bottom
C88 "0.1uf, 6V3" 402 1800,945.25 r270 bottom
C89 "1uF, 10V" 402 1825,775 r270 bottom
C90 "1uF, 10V" 402 1750,775 r270 bottom
C91 "1uF, 10V" 402 1787.5,775 r270 bottom
C92 "0.1uf, 6V3" 402 1900,775 r270 bottom
C93 "0.1uf, 6V3" 402 1775,700 r270 top
C94 "0.1uf, 6V3" 402 1737,1260.25 r270 bottom
C95 "10uF, 10V" 805 2125,750 r90 bottom
C96 "10uF, 10V" 805 2180,540 r90 top
C97 "0.1uf, 6V3" 402 1941.75,1213 r180 bottom
C98 "0.1uf, 6V3" 402 1941.72,1150 r180 bottom
C99 "0.1uf, 6V3" 402 1941.75,1087 r180 bottom
C100 "0.1uf, 6V3" 402 1941.75,1024 r180 bottom
C101 "0.1uf, 6V3" 402 2050,775 r270 bottom
C102 "0.1uf, 6V3" 402 2100,637.5 r90 bottom
C103 "0.1uf, 6V3" 402 2150,637.5 r90 bottom
C104 "1uF, 10V" 402 1937.5,775 r270 bottom
C105 "0.1uf, 6V3" 402 1862.5,775 r270 bottom
C106 "0.1uf, 6V3" 402 1721.26,1449.25 r90 bottom
C107 "0.1uf, 6V3" 402 2300,1227 r180 bottom
C108 "0.1uf, 6V3" 402 2300,1164 r180 bottom
C109 "0.1uf, 6V3" 402 2300,1069.5 r180 bottom
C110 "0.1uf, 6V3" 402 2300,1006.5 r180 bottom
C111 "0.1uf, 6V3" 402 2300,912 r180 bottom
C112 "0.1uf, 6V3" 402 2300,817.5 r180 bottom
C113 "0.1uf, 6V3" 402 2300,754.5 r180 bottom
C114 "0.1uf, 6V3" 402 2700,1227 r0 bottom
C115 "0.1uf, 6V3" 402 2700,1164 r0 bottom
C116 "0.1uf, 6V3" 402 2700,1101 r0 bottom
C117 "0.1uf, 6V3" 402 2700,1006.5 r0 bottom
C118 "10uF, 10V" 805 2675,1287.5 r180 bottom
C119 "0.1uf, 6V3" 402 2700,959.25 r0 bottom
C120 "0.1uf, 6V3" 402 2700,817.5 r0 bottom
C121 "0.1uf, 6V3" 402 2700,754.5 r0 bottom
C122 "10uF, 10V" 805 2675,662.5 r180 bottom
C123 "1nF, 50V" 402 2500,959.25 r0 bottom
C124 "0.1uf, 6V3" 402 2500,864.75 r180 bottom
C125 "2.2uF, 6V3" 402 1275,1850 r90 bottom
C126 "10uF, 10V" 805 925,1650 r90 bottom
C127 "0.1uf, 6V3" 402 1000,1650 r270 bottom
C128 "0.1uf, 6V3" 402 1150,1650 r90 bottom
C129 "0.1uf, 6V3" 402 1200,1650 r270 bottom
C130 "0.1uf, 6V3" 402 1350,1650 r270 bottom
C131 "0.1uf, 6V3" 402 925,1125 r0 bottom
C132 "0.1uf, 6V3" 402 925,1175 r0 bottom
C133 "10uF, 10V" 805 925,1312.5 r180 bottom
C134 "1uF, 10V" 402 1050,1125 r180 bottom
C135 "0.1uf, 6V3" 402 1050,1325 r0 bottom
C136 "470pF, 50V" 402 1050,1175 r180 bottom
C137 "15pF, DNI" 402 475,1350 r180 bottom
C138 "15pF, DNI" 402 475,1300 r180 bottom
C139 "15pF, DNI" 402 475,1250 r180 bottom
C140 "15pF, DNI" 402 475,1100 r180 bottom
C141 "0.022uF,10V" 402 475,1200 r180 bottom
C142 "30pF, 50V" 402 912.5,1012.5 r90 bottom
C143 "30pF, 50V" 402 1062.5,1012.5 r90 bottom
C144 "2.2uF, 6V3" 402 2325,1600 r270 bottom
C145 "0.1uf, 6V3" 402 2325,1425 r270 bottom
C146 "2.2uF, 6V3" 402 2525,1725 r270 bottom
C147 "0.1uf, 6V3" 402 2575,1425 r90 bottom
C148 "2.2uF, 6V3" 402 2575,1725 r270 bottom
C149 "0.1uf, 6V3" 402 2675,1725 r90 bottom
C150 "0.1uf, 6V3" 402 2675,1600 r90 bottom
C151 "2.2uF, 6V3" 402 2625,1425 r270 bottom
C152 "0.1uf, 6V3" 402 1025,862.5 r90 bottom
C153 "10uF, 10V" 805 3200,1485 r90 top
C154 "0.1uf, 6V3" 402 3275,1485 r90 top
C155 "0.1uf, 6V3" 402 2180,450 r270 bottom
C156 "47pF, 6.3V" 402 2175,1730 r90 top
C157 "47pF, 6.3V" 402 2125,1590 r90 top
C158 "0.1uf, 6V3" 402 1562.5,1850 r90 bottom
C159 "0.1uf, 6V3" 402 1562.5,1650 r270 bottom
C160 "47pF, 6.3V" 402 2175,1590 r270 top
C161 "47pF, 6.3V" 402 2025,1590 r90 bottom
C162 "47pF, 6.3V" 402 2075,1590 r90 bottom
C163 "47pF, 6.3V" 402 2225,1590 r90 top
C164 "47pF, 6.3V" 402 1975,1590 r90 bottom
C165 "47pF, 6.3V" 402 2175,1850 r270 top
C166 "47pF, 6.3V" 402 2075,1590 r90 top
C167 "47pF, 6.3V" 402 2125,1730 r270 top
C168 "47pF, 6.3V" 402 2075,1730 r90 top
C169 "47pF, 6.3V" 402 2225,1470 r270 top
C170 "47pF, 6.3V" 402 2125,1590 r90 bottom
C171 "47pF, 6.3V" 402 2975,1850 r270 bottom
C172 "47pF, 6.3V" 402 2175,1590 r90 bottom
C173 "47pF, 6.3V" 402 2975,1850 r270 top
D1 "598-8170-107F" LED_0603 150,625 r0 top
D2 "598-8170-107F" LED_0603 125,1862.5 r0 top
D3 "598-8170-107F" LED_0603 125,1787.5 r0 top
D4 "598-8170-107F" LED_0603 125,1712.5 r0 top
D5 "598-8170-107F" LED_0603 125,1637.5 r0 top
D6 "IP4283CZ10-TT" TSSOP10 2975,1375 r270 top
D7 "IP4283CZ10-TT" TSSOP10 2975,1550 r270 top
D8 "RB751V40,115" SOD323 2875,1175 r90 top
FB1 "150OHM800mA" SM-7351-IND-0805 1350,1262.5 r180 bottom
FB2 "150OHM800mA" SM-7351-IND-0805 1825,637.5 r90 bottom
FB3 "150OHM800mA" SM-7351-IND-0805 1725,637.5 r90 bottom
FB4 "150OHM800mA" SM-7351-IND-0805 925,1412.5 r0 bottom
FB5 "150OHM800mA" SM-7351-IND-0805 2200,1450 r90 bottom
FB7 "150OHM800mA" SM-7351-IND-0805 2675,440 r180 bottom
FB8 "0.1 Ohm, 0805" SM-7351-IND-0805 2520,440 r180 bottom
J1 "HEADER 6" SIP6 1925,300 r90 top
L1 "2.2uH, 2.6A" 2520 847.5,337.5 r0 bottom
L2 "2.2uH, 2.6A" 2520 1010,337.5 r180 bottom
L3 "2.2uH, 2.6A" 2520 1137.5,600 r90 bottom
MTG1 "MHOLE" MTGH200C125D_PL 575,140.5 r90 top
MTG2 "MHOLE" MTGH200C125D_PL 3175,265.5 r90 top
MTG3 "MHOLE" MTGH200C125D_PL 575,2040.5 r90 top
MTG4 "MHOLE" MTGH200C125D_PL 3175,1915.5 r90 top
P1 "PJ-200A" CONN3-PWR-PJ102A 195,375 r180 top
P2 "CTI JTAG,DNI" HEADER10X2_SMD 1387.5,512.5 r270 bottom
P3 "USB-A Conn. - 87520-xx1xx" USB_A_SH 3123.2,662.1 r90 top
P4 "mini USB-B" USB5MINI_4SHIELDED_SMD-5 121.89,1737.5 r180 bottom
P5 "WE_7499010211A" RJ45-7499010211A 322.5,1175 r270 top
P6 "10118241-001RLF" CONN19_HDMI 3273.62,990 r90 bottom
P8 "FEMALE HEADER 2x23" HEADER23X2 1875,2025 r0 top
P9 "FEMALE HEADER 2x23" HEADER23X2 1875,125 r0 top
P10 "MOLEX 502570-001" SD-MICRO-SCHA5B0300 3082.41,1485 r90 bottom
Q1 "DMC56404" SMINI6-F3-B 512.5,1825 r180 top
Q2 "DMC56404" SMINI6-F3-B 375,1825 r180 top
R1 "100K, 1%" 402 912.5,862.5 r270 bottom
R3 "1.5K, 1%" 402 1025,862.5 r270 top
R4 "1.5K, 1%" 402 1062.5,862.5 r270 top
R5 "0R, 1%" 402 637.5,625 r180 top
R6 "0R, 1%" 402 740,340 r270 bottom
R7 "0R, 1%" 402 450,625 r180 top
R8 "0R, 1%" 402 450,675 r180 top
R9 "0R, 1%, DNI" 402 450,725 r0 top
R10 "470K, 5%" 402 325,675 r180 top
R11 "280K, 1%" 402 325,725 r0 bottom
R12 "820, 5%" 402 150,650 r180 bottom
R14 "10K, 1%" 402 1137.5,475 r180 bottom
R17 "1M, 1%" 402 1779.96,1535 r180 bottom
R18 "33, 0402" 402 1650,450 r270 bottom
R19 "0R, 1%" 402 1637.5,775 r270 bottom
R20 "0R, 1%" 402 1675,775 r90 bottom
R21 "33, 0402" 402 1900,450 r270 bottom
R22 "49.9, 1%" 402 2200,1118.5 r180 bottom
R23 "4.75K, 1%" 402 1450,487.5 r270 top
R24 "4.75K, 1%" 402 1450,575 r90 top
R25 "4.75K, 1%" 402 1450,337.5 r90 top
R26 "4.75K, 1%" 402 1975,775 r90 bottom
R27 "0R, 1%" 402 1756.25,762.5 r180 top
R28 "33, 0402" 402 1350,1095 r180 top
R45 "33, 0402" 402 1975,1730 r90 top
R46 "33, 0402" 402 2025,1730 r90 top
R47 "33, 0402" 402 2025,1590 r90 top
R48 "33, 0402" 402 1975,1590 r90 top
R49 "0R, 1%" 402 1500,1337.5 r0 bottom
R50 "0R, 1%" 402 1450,700 r270 top
R51 "0R, 1%" 402 1600,775 r90 bottom
R52 "10k, 1%" 402 3273.9,725 r270 bottom
R53 "10k, 1%" 402 3023.9,725 r90 bottom
R54 "10k, 1%" 402 2012.5,775 r90 bottom
R55 "100K, 1%, DNI" 402 2300,1850 r90 bottom
R56 "100K, 1%" 402 2262.5,1850 r90 bottom
R57 "100K, 1%, DNI" 402 2375,1850 r90 bottom
R58 "100K, 1%,DNI" 402 2412.5,1850 r90 bottom
R59 "100K, 1%, DNI" 402 2337.5,1850 r90 bottom
R60 "100K, 1%,DNI" 402 2450,1850 r90 bottom
R61 "100K, 1%,DNI" 402 2487.5,1850 r90 bottom
R62 "100K, 1%,DNI" 402 2525,1850 r90 bottom
R63 "100K, 1%,DNI" 402 2562.5,1850 r90 bottom
R64 "100K, 1%,DNI" 402 2600,1850 r90 bottom
R65 "100K, 1%" 402 2637.5,1850 r90 bottom
R66 "100K, 1%" 402 2675,1850 r90 bottom
R67 "100K, 1%" 402 2712.5,1850 r90 bottom
R68 "100K, 1%" 402 2750,1850 r90 bottom
R69 "100K, 1%, DNI" 402 2787.5,1850 r90 bottom
R70 "100K, 1%,DNI" 402 2825,1850 r90 bottom
R71 "820, 5%" 402 250,1750 r180 top
R72 "820, 5%" 402 250,1862.5 r180 top
R73 "820, 5%" 402 250,1825 r180 top
R74 "820, 5%" 402 250,1787.5 r180 top
R75 "100" 402 2900,1850 r270 top
R76 "100K, 1%" 402 512.5,1812.5 r90 bottom
R77 "100K, 1%" 402 562.5,1812.5 r270 bottom
R78 "100K, 1%" 402 375,1812.5 r90 bottom
R79 "100K, 1%" 402 425,1812.5 r270 bottom
R80 "100K, 1%" 402 2300,1850 r270 top
R81 "100K, 1%, DNI" 402 2262.5,1850 r270 top
R82 "100K, 1%" 402 2375,1850 r270 top
R83 "100K, 1%" 402 2412.5,1850 r270 top
R84 "100K, 1%" 402 2337.5,1850 r270 top
R85 "100K, 1%" 402 2450,1850 r270 top
R86 "100K, 1%" 402 2487.5,1850 r270 top
R87 "100K, 1%" 402 2525,1850 r270 top
R88 "100K, 1%" 402 2562.5,1850 r270 top
R89 "100K, 1%" 402 2600,1850 r270 top
R90 "100K, 1%, DNI" 402 2637.5,1850 r270 top
R91 "100K, 1%, DNI" 402 2675,1850 r270 top
R92 "100K, 1%, DNI" 402 2712.5,1850 r270 top
R93 "100K, 1%, DNI" 402 2750,1850 r270 top
R94 "100K, 1%" 402 2787.5,1850 r270 top
R95 "100K, 1%" 402 2825,1850 r270 top
R96 "10k, 1%" 402 2700,912 r180 bottom
R97 "1.5K, 1%" 402 2500,754.5 r180 bottom
R98 "10k, 1%" 402 2500,1006.5 r180 bottom
R99 "240, 1%" 402 2700,864.75 r180 bottom
R100 "10k, 1%" 402 2500,912 r180 bottom
R101 "10k, 1%" 402 1925,1850 r90 bottom
R102 "10k, 1%" 402 1825,1850 r90 bottom
R103 "10k, 1%" 402 1025,1850 r90 bottom
R104 "10k, 1%" 402 1075,1850 r90 bottom
R105 "10k, 1%" 402 1875,1850 r90 bottom
R106 "10k, 1%" 402 1725,1850 r90 bottom
R107 "10k, 1%" 402 925,1850 r90 bottom
R108 "10k, 1%" 402 975,1850 r90 bottom
R109 "10k, 1%" 402 1675,1850 r90 bottom
R110 "10k, 1%" 402 1775,1850 r90 bottom
R111 "10k, 1%" 402 1150,1850 r270 bottom
R112 "1.5K, 1%" 402 1200,1212.5 r0 bottom
R113 "1.5K, 1%" 402 1200,1325 r0 bottom
R114 "1.5K, 1%" 402 1200,1175 r0 bottom
R115 "10k, 1%" 402 1200,1250 r0 bottom
R116 "10k, 1%" 402 1200,1100 r0 bottom
R117 "10k, 1%" 402 1200,1137.5 r0 bottom
R118 "10k, 1%" 402 1200,1025 r0 top
R119 "1.5K, 1%" 402 1200,1325 r180 top
R120 "49.9, 1%" 402 787.5,1150 r180 bottom
R121 "49.9, 1%" 402 787.5,1187.5 r180 bottom
R122 "49.9, 1%" 402 787.5,1225 r180 bottom
R123 "49.9, 1%" 402 787.5,1262.5 r180 bottom
R124 "10, 1%,DNI" 402 1200,1062.5 r180 top
R125 "100, 1%" 402 1200,1100 r180 top
R126 "100, 1%" 402 1200,1137.5 r180 top
R127 "100, 1%" 402 1200,1175 r180 top
R128 "100, 1%" 402 1200,1212.5 r180 top
R129 "100, 1%" 402 787.5,1325 r0 bottom
R130 "470, 5%" 402 225,1100 r180 bottom
R131 "100, 1%" 402 1200,1062.5 r180 bottom
R132 "470, 5%" 402 225,1250 r180 bottom
R133 "100, 1%" 402 1200,1250 r180 top
R134 "100, 1%" 402 1200,1400 r180 bottom
R135 "10k, 1%" 402 225,1050 r0 bottom
R136 "0.1, 0805" 805 162.5,1175 r180 bottom
R137 "0R, 1%" 402 475,1150 r180 bottom
R138 "100, 1%" 402 1200,1287.5 r180 bottom
R139 "100, 1%" 402 1200,1287.5 r180 top
R140 "0R, 1%,DNI" 402 1200,1025 r180 bottom
R141 "1M, 1%,DNI" 402 987.5,1012.5 r270 bottom
R142 "0R, 1%" 402 1025,1012.5 r90 bottom
R143 "10, 1%" 402 950,1012.5 r270 bottom
R144 "12.1K, 1%" 402 787.5,1112.5 r180 bottom
R145 "10k, 1%" 402 1200,1362.5 r0 bottom
R146 "1.5K, 1%" 402 3025,1062.5 r0 bottom
R147 "1.5K, 1%" 402 3025,1112.5 r0 bottom
R148 "10k, 1%" 402 2675,1425 r270 bottom
R149 "0R, 1%" 402 2625,1725 r270 bottom
R150 "10k, 1%" 402 3200,1660 r90 top
R151 "10k, 1%" 402 3275,1660 r90 top
R152 "10k, 1%" 402 3275,1310 r270 top
R153 "10k, 1%" 402 3237.5,1310 r270 top
R154 "10k, 1%" 402 3200,1310 r270 top
R155 "10k, 1%" 402 3237.5,1660 r90 top
R156 "10k, 1%" 402 987.5,862.5 r90 bottom
R157 "10k, 1%" 402 2825,1700 r270 top
R158 "10k, 1%" 402 1500,1512.5 r180 bottom
R159 "0R, 1%" 402 925,1512.5 r0 bottom
R160 "0R, 1%" 402 1512.5,1650 r90 bottom
R161 "0R, 1%" 402 1462.5,1650 r90 bottom
R162 "0R, 1%" 402 1200,1850 r270 bottom
R163 "4.75K, 1%" 402 1887.5,637.5 r90 bottom
R164 "4.75K, 1%" 402 1937.5,637.5 r90 bottom
R165 "100K, 1%" 402 1825,450 r90 top
R166 "27K, 1%" 402 2875,1050 r270 top
R167 "33, 0402" 402 1612.5,1650 r270 bottom
RT1 "PTC_RXEF010" POLYSW200-5638-310 2725,425 r90 top
S1 "KMR231GLFS" SW4SMD_63X161LS 312.5,2025 r180 top
S2 "KMR231GLFS" SW4SMD_63X161LS 2975,1700 r180 top
S3 "KMR231GLFS" SW4SMD_63X161LS 312.5,1650 r180 top
TP1 "TESTPT1" TP1-8040 2325,425 r0 top
TP2 "TESTPT1" TP60C_SMD 2262.5,612.5 r0 top
TP3 "TESTPT1" TP60C_SMD 2025,775 r0 top
TP4 "TESTPT1" TP1-8040 150,750 r0 top
TP5 "TESTPT1" TP60C33D 580,420 r0 top
TP6 "TESTPT1" TP60C33D 580,320 r0 top
TP7 "TESTPT1" TP60C33D 680,420 r0 top
TP8 "TESTPT1" TP60C33D 680,320 r0 top
U2 "TPS65217C" U_48_RSL 900,600 r0 top
U3 "SN74LVC1G06DCK" DCK5_2P15X1P4 1587.5,1800 r0 top
U4 "TL5209" SO8-25X75 537.5,650 r270 bottom
U5 "IC_AM335X_ZCE_1" AM33XX_15X15 1800,1150 r180 top
U6 "SN74LVC1G74DCTR" SOP8_DCT 1775,450 r270 bottom
U7 "24LC32A" SOT23-5 1162.5,862.5 r90 bottom
U8 "TPS2051 (DGN)" DGN-16X60 3123.9,575 r270 bottom
U9 "TPD4S012" U_6_DRY 3123.9,725 r90 bottom
U10 "TPD4S012" U_6_DRY 512.5,1650 r270 top
U11 "TDA19988" QFN64S9X9P5 2500,1575 r0 top
U12 "MT41K256M16HA -125:E" BGA96_T9_P8_9X14 2500,975 r0 top
U13 "eMMC, 2GB" BGA153_P14_P5_11P5X13 1175,1650 r270 top
U14 "LAN8710A" QFN32_5X5MM_EP3P3MM 987.5,1225 r0 top
U15 "SN74LVC2G241" U_8_DCU 2070,450 r270 bottom
Y1 "32.768kHz" XTAL4_126-216SMD 2012.5,550 r270 top
Y2 "24MHz" XTAL150SMD_125X196 1780,1630 r0 bottom
Y3 "25.000MHz" XTAL150SMD_125X196 987.5,1012.5 r180 top
Y4 "24.576MHz" OSC4_61X65LS_79X98SMD 1587.5,1637.5 r0 top

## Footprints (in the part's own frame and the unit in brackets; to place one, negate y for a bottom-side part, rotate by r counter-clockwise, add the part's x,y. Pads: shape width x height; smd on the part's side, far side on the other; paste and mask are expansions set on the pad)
402 [mil] "402"
  rect 25x20 smd mask+2: 1(-20,0) 2(20,0)
  silkscreen extent -40,-15 40,15
805 [mil] "805"
  rect 45x50 smd mask+2: 1(-35,0) 2(35,0)
  silkscreen extent -65,-35 65,35
2520 [mil] "2520"
  rect 45x75 smd mask+2: 1(45,0) 2(-45,0)
  silkscreen extent -80,-50 80,50
AM33XX_15X15 [mil] "AM33XX_15X15"
  round 14 smd mask+0: A1(-267.72,267.72) A2(-236.22,267.72) A3(-204.72,267.72) A4(-173.23,267.72) A5(-141.73,267.72) A6(-110.24,267.72) A7(-78.74,267.72) A8(-47.24,267.72) A9(-15.75,267.72) A10(15.75,267.72) A11(47.24,267.72) A12(78.74,267.72) A13(110.24,267.72) A14(141.73,267.72) A15(173.23,267.72) A16(204.72,267.72) A17(236.22,267.72) A18(267.72,267.72) B1(-267.72,236.22) B2(-236.22,236.22) B3(-204.72,236.22) B4(-173.23,236.22) B5(-141.73,236.22) B6(-110.24,236.22) B7(-78.74,236.22) B8(-47.24,236.22) B9(-15.75,236.22) B10(15.75,236.22) B11(47.24,236.22) B12(78.74,236.22) B13(110.24,236.22) B14(141.73,236.22) B15(173.23,236.22) B16(204.72,236.22) B17(236.22,236.22) B18(267.72,236.22) C1(-267.72,204.72) C2(-236.22,204.72) C3(-204.72,204.72) C4(-173.23,204.72) C5(-141.73,204.72) C6(-110.24,204.72) C7(-78.74,204.72) C8(-47.24,204.72) C9(-15.75,204.72) C10(15.75,204.72) C11(47.24,204.72) C12(78.74,204.72) C13(110.24,204.72) C14(141.73,204.72) C15(173.23,204.72) C16(204.72,204.72) C17(236.22,204.72) C18(267.72,204.72) D1(-267.72,173.23) D2(-236.22,173.23) D3(-204.72,173.23) D4(-173.23,173.23) D5(-141.73,173.23) D6(-110.24,173.23) D7(-78.74,173.23) D8(-47.24,173.23) D9(-15.75,173.23) D10(15.75,173.23) D11(47.24,173.23) D12(78.74,173.23) D13(110.24,173.23) D14(141.73,173.23) D15(173.23,173.23) D16(204.72,173.23) D17(236.22,173.23) D18(267.72,173.23) E1(-267.72,141.73) E2(-236.22,141.73) E3(-204.72,141.73) E4(-173.23,141.73) E5(-141.73,141.73) E6(-110.24,141.73) E7(-78.74,141.73) E8(-47.24,141.73) E9(-15.75,141.73) E10(15.75,141.73) E11(47.24,141.73) E12(78.74,141.73) E13(110.24,141.73) E14(141.73,141.73) E15(173.23,141.73) E16(204.72,141.73) E17(236.22,141.73) E18(267.72,141.73) F1(-267.72,110.24) F2(-236.22,110.24) F3(-204.72,110.24) F4(-173.23,110.24) F5(-141.73,110.24) F6(-110.24,110.24) F7(-78.74,110.24) F8(-47.24,110.24) F9(-15.75,110.24) F10(15.75,110.24) F11(47.24,110.24) F12(78.74,110.24) F13(110.24,110.24) F14(141.73,110.24) F15(173.23,110.24) F16(204.72,110.24) F17(236.22,110.24) F18(267.72,110.24) G1(-267.72,78.74) G2(-236.22,78.74) G3(-204.72,78.74) G4(-173.23,78.74) G5(-141.73,78.74) G6(-110.24,78.74) G7(-78.74,78.74) G8(-47.24,78.74) G9(-15.75,78.74) G10(15.75,78.74) G11(47.24,78.74) G12(78.74,78.74) G13(110.24,78.74) G14(141.73,78.74) G15(173.23,78.74) G16(204.72,78.74) G17(236.22,78.74) G18(267.72,78.74) H1(-267.72,47.24) H2(-236.22,47.24) H3(-204.72,47.24) H4(-173.23,47.24) H5(-141.73,47.24) H6(-110.24,47.24) H7(-78.74,47.24) H8(-47.24,47.24) H9(-15.75,47.24) H10(15.75,47.24) H11(47.24,47.24) H12(78.74,47.24) H13(110.24,47.24) H14(141.73,47.24) H15(173.23,47.24) H16(204.72,47.24) H17(236.22,47.24) H18(267.72,47.24) J1(-267.72,15.75) J2(-236.22,15.75) J3(-204.72,15.75) J4(-173.23,15.75) J5(-141.73,15.75) J6(-110.24,15.75) J7(-78.74,15.75) J8(-47.24,15.75) J9(-15.75,15.75) J10(15.75,15.75) J11(47.24,15.75) J12(78.74,15.75) J13(110.24,15.75) J14(141.73,15.75) J15(173.23,15.75) J16(204.72,15.75) J17(236.22,15.75) J18(267.72,15.75) K1(-267.72,-15.75) K2(-236.22,-15.75) K3(-204.72,-15.75) K4(-173.23,-15.75) K5(-141.73,-15.75) K6(-110.24,-15.75) K7(-78.74,-15.75) K8(-47.24,-15.75) K9(-15.75,-15.75) K10(15.75,-15.75) K11(47.24,-15.75) K12(78.74,-15.75) K13(110.24,-15.75) K14(141.73,-15.75) K15(173.23,-15.75) K16(204.72,-15.75) K17(236.22,-15.75) K18(267.72,-15.75) L1(-267.72,-47.24) L2(-236.22,-47.24) L3(-204.72,-47.24) L4(-173.23,-47.24) L5(-141.73,-47.24) L6(-110.24,-47.24) L7(-78.74,-47.24) L8(-47.24,-47.24) L9(-15.75,-47.24) L10(15.75,-47.24) L11(47.24,-47.24) L12(78.74,-47.24) L13(110.24,-47.24) L14(141.73,-47.24) L15(173.23,-47.24) L16(204.72,-47.24) L17(236.22,-47.24) L18(267.72,-47.24) M1(-267.72,-78.74) M2(-236.22,-78.74) M3(-204.72,-78.74) M4(-173.23,-78.74) M5(-141.73,-78.74) M6(-110.24,-78.74) M7(-78.74,-78.74) M8(-47.24,-78.74) M9(-15.75,-78.74) M10(15.75,-78.74) M11(47.24,-78.74) M12(78.74,-78.74) M13(110.24,-78.74) M14(141.73,-78.74) M15(173.23,-78.74) M16(204.72,-78.74) M17(236.22,-78.74) M18(267.72,-78.74) N1(-267.72,-110.24) N2(-236.22,-110.24) N3(-204.72,-110.24) N4(-173.23,-110.24) N5(-141.73,-110.24) N6(-110.24,-110.24) N7(-78.74,-110.24) N8(-47.24,-110.24) N9(-15.75,-110.24) N10(15.75,-110.24) N11(47.24,-110.24) N12(78.74,-110.24) N13(110.24,-110.24) N14(141.73,-110.24) N15(173.23,-110.24) N16(204.72,-110.24) N17(236.22,-110.24) N18(267.72,-110.24) P1(-267.72,-141.73) P2(-236.22,-141.73) P3(-204.72,-141.73) P4(-173.23,-141.73) P5(-141.73,-141.73) P6(-110.24,-141.73) P7(-78.74,-141.73) P8(-47.24,-141.73) P9(-15.75,-141.73) P10(15.75,-141.73) P11(47.24,-141.73) P12(78.74,-141.73) P13(110.24,-141.73) P14(141.73,-141.73) P15(173.23,-141.73) P16(204.72,-141.73) P17(236.22,-141.73) P18(267.72,-141.73) R1(-267.72,-173.23) R2(-236.22,-173.23) R3(-204.72,-173.23) R4(-173.23,-173.23) R5(-141.73,-173.23) R6(-110.24,-173.23) R7(-78.74,-173.23) R8(-47.24,-173.23) R9(-15.75,-173.23) R10(15.75,-173.23) R11(47.24,-173.23) R12(78.74,-173.23) R13(110.24,-173.23) R14(141.73,-173.23) R15(173.23,-173.23) R16(204.72,-173.23) R17(236.22,-173.23) R18(267.72,-173.23) T1(-267.72,-204.72) T2(-236.22,-204.72) T3(-204.72,-204.72) T4(-173.23,-204.72) T5(-141.73,-204.72) T6(-110.24,-204.72) T7(-78.74,-204.72) T8(-47.24,-204.72) T9(-15.75,-204.72) T10(15.75,-204.72) T11(47.24,-204.72) T12(78.74,-204.72) T13(110.24,-204.72) T14(141.73,-204.72) T15(173.23,-204.72) T16(204.72,-204.72) T17(236.22,-204.72) T18(267.72,-204.72) U1(-267.72,-236.22) U2(-236.22,-236.22) U3(-204.72,-236.22) U4(-173.23,-236.22) U5(-141.73,-236.22) U6(-110.24,-236.22) U7(-78.74,-236.22) U8(-47.24,-236.22) U9(-15.75,-236.22) U10(15.75,-236.22) U11(47.24,-236.22) U12(78.74,-236.22) U13(110.24,-236.22) U14(141.73,-236.22) U15(173.23,-236.22) U16(204.72,-236.22) U17(236.22,-236.22) U18(267.72,-236.22) V1(-267.72,-267.72) V2(-236.22,-267.72) V3(-204.72,-267.72) V4(-173.23,-267.72) V5(-141.73,-267.72) V6(-110.24,-267.72) V7(-78.74,-267.72) V8(-47.24,-267.72) V9(-15.75,-267.72) V10(15.75,-267.72) V11(47.24,-267.72) V12(78.74,-267.72) V13(110.24,-267.72) V14(141.73,-267.72) V15(173.23,-267.72) V16(204.72,-267.72) V17(236.22,-267.72) V18(267.72,-267.72)
  silkscreen extent -295,-295 295,295
BGA96_T9_P8_9X14 [mil] "BGA96_T9_P8_9X14"
  round 14 smd mask+2: A1(-126,236.25) A2(-94.5,236.25) A3(-63,236.25) A7(63,236.25) A8(94.5,236.25) A9(126,236.25) B1(-126,204.75) B2(-94.5,204.75) B3(-63,204.75) B7(63,204.75) B8(94.5,204.75) B9(126,204.75) C1(-126,173.25) C2(-94.5,173.25) C3(-63,173.25) C7(63,173.25) C8(94.5,173.25) C9(126,173.25) D1(-126,141.75) D2(-94.5,141.75) D3(-63,141.75) D7(63,141.75) D8(94.5,141.75) D9(126,141.75) E1(-126,110.25) E2(-94.5,110.25) E3(-63,110.25) E7(63,110.25) E8(94.5,110.25) E9(126,110.25) F1(-126,78.75) F2(-94.5,78.75) F3(-63,78.75) F7(63,78.75) F8(94.5,78.75) F9(126,78.75) G1(-126,47.25) G2(-94.5,47.25) G3(-63,47.25) G7(63,47.25) G8(94.5,47.25) G9(126,47.25) H1(-126,15.75) H2(-94.5,15.75) H3(-63,15.75) H7(63,15.75) H8(94.5,15.75) H9(126,15.75) J1(-126,-15.75) J2(-94.5,-15.75) J3(-63,-15.75) J7(63,-15.75) J8(94.5,-15.75) J9(126,-15.75) K1(-126,-47.25) K2(-94.5,-47.25) K3(-63,-47.25) K7(63,-47.25) K8(94.5,-47.25) K9(126,-47.25) L1(-126,-78.75) L2(-94.5,-78.75) L3(-63,-78.75) L7(63,-78.75) L8(94.5,-78.75) L9(126,-78.75) M1(-126,-110.25) M2(-94.5,-110.25) M3(-63,-110.25) M7(63,-110.25) M8(94.5,-110.25) M9(126,-110.25) N1(-126,-141.75) N2(-94.5,-141.75) N3(-63,-141.75) N7(63,-141.75) N8(94.5,-141.75) N9(126,-141.75) P1(-126,-173.25) P2(-94.5,-173.25) P3(-63,-173.25) P7(63,-173.25) P8(94.5,-173.25) P9(126,-173.25) R1(-126,-204.75) R2(-94.5,-204.75) R3(-63,-204.75) R7(63,-204.75) R8(94.5,-204.75) R9(126,-204.75) T1(-126,-236.25) T2(-94.5,-236.25) T3(-63,-236.25) T7(63,-236.25) T8(94.5,-236.25) T9(126,-236.25)
  TOP lines w4.75: -141.75,-63 -126,-47.25 ; -141.75,31.5 -126,15.75 ; -110.25,-252 -94.5,-236.25 ; -110.25,-220.5 -94.5,-204.75 ; -110.25,-189 -94.5,-173.25 ; -110.25,-157.5 -94.5,-141.75 ; -110.25,-126 -94.5,-110.25 ; -110.25,189 -94.5,173.25 ; -110.25,252 -94.5,236.25 ; -78.75,-252 -63,-236.25 ; -78.75,-220.5 -63,-204.75 ; -78.75,-189 -63,-173.25 ; -78.75,-157.5 -63,-141.75 ; -78.75,-126 -63,-110.25 ; -78.75,-94.5 -63,-78.75 ; -78.75,-31.5 -63,-15.75 ; -63,110.25 -47.25,126 ; 63,-236.25 78.75,-252 ; 63,-204.75 78.75,-220.5 ; 63,-173.25 78.75,-189 ; 63,-141.75 78.75,-157.5 ; 63,-78.75 78.75,-94.5 ; 63,15.75 78.75,31.5 ; 63,78.75 78.75,94.5 ; 63,110.25 78.75,126 ; 63,173.25 78.75,189 ; 63,204.75 78.75,220.5 ; 63,236.25 78.75,252 ; 94.5,-236.25 110.25,-252 ; 94.5,-204.75 110.25,-220.5 ; 94.5,-173.25 110.25,-189 ; 94.5,-141.75 110.25,-157.5 ; 94.5,-110.25 110.25,-126 ; 94.5,-78.75 110.25,-94.5 ; 94.5,15.75 110.25,31.5 ; 94.5,78.75 110.25,94.5 ; 94.5,173.25 110.25,189 ; 94.5,204.75 110.25,220.5 ; 126,-47.25 141.75,-63
  TOP lines w10: -141.75,-252 -126,-236.25 ; -141.75,-220.5 -126,-204.75 ; -141.75,-189 -126,-173.25 ; -141.75,-157.5 -126,-141.75 ; -141.75,-126 -126,-110.25 ; -141.75,94.5 -126,78.75 ; -141.75,189 -126,173.25 ; -141.75,220.5 -126,204.75 ; -141.75,252 -126,236.25 ; -126,110.25 -110.25,94.5 ; -110.25,-63 -94.5,-47.25 ; -110.25,-31.5 -94.5,-15.75 ; -110.25,31.5 -94.5,15.75 ; -110.25,126 -94.5,110.25 ; -110.25,220.5 -94.5,204.75 ; -94.5,141.75 -78.75,126 ; -78.75,220.5 -63,204.75 ; 63,47.25 78.75,63 ; 94.5,-47.25 110.25,-63 ; 94.5,-15.75 110.25,-31.5 ; 94.5,47.25 110.25,63 ; 94.5,110.25 110.25,126 ; 94.5,141.75 110.25,157.5 ; 94.5,236.25 110.25,252 ; 126,-236.25 141.75,-252 ; 126,-204.75 141.75,-220.5 ; 126,-173.25 141.75,-189 ; 126,-141.75 141.75,-157.5 ; 126,-110.25 141.75,-126 ; 126,15.75 141.75,31.5 ; 126,47.25 141.75,63 ; 126,110.25 141.75,126 ; 126,141.75 141.75,157.5 ; 126,173.25 141.75,189 ; 126,204.75 141.75,220.5
  silkscreen extent -177,-276 177,276
BGA153_P14_P5_11P5X13 [mil] "BGA153_P14_P5_11P5X13"
  round 10 smd mask+2: A1(-127.95,127.95) A2(-108.27,127.95) A3(-88.58,127.95) A4(-68.9,127.95) A5(-49.21,127.95) A6(-29.53,127.95) A7(-9.84,127.95) A8(9.84,127.95) A9(29.53,127.95) A10(49.21,127.95) A11(68.9,127.95) A12(88.58,127.95) A13(108.27,127.95) A14(127.95,127.95) B1(-127.95,108.27) B2(-108.27,108.27) B3(-88.58,108.27) B4(-68.9,108.27) B5(-49.21,108.27) B6(-29.53,108.27) B7(-9.84,108.27) B8(9.84,108.27) B9(29.53,108.27) B10(49.21,108.27) B11(68.9,108.27) B12(88.58,108.27) B13(108.27,108.27) B14(127.95,108.27) C1(-127.95,88.58) C2(-108.27,88.58) C3(-88.58,88.58) C4(-68.9,88.58) C5(-49.21,88.58) C6(-29.53,88.58) C7(-9.84,88.58) C8(9.84,88.58) C9(29.53,88.58) C10(49.21,88.58) C11(68.9,88.58) C12(88.58,88.58) C13(108.27,88.58) C14(127.95,88.58) D1(-127.95,68.9) D2(-108.27,68.9) D3(-88.58,68.9) D4(-68.9,68.9) D12(88.58,68.9) D13(108.27,68.9) D14(127.95,68.9) E1(-127.95,49.21) E2(-108.27,49.21) E3(-88.58,49.21) E5(-49.21,49.21) E6(-29.53,49.21) E7(-9.84,49.21) E8(9.84,49.21) E9(29.53,49.21) E10(49.21,49.21) E12(88.58,49.21) E13(108.27,49.21) E14(127.95,49.21) F1(-127.95,29.53) F2(-108.27,29.53) F3(-88.58,29.53) F5(-49.21,29.53) F10(49.21,29.53) F12(88.58,29.53) F13(108.27,29.53) F14(127.95,29.53) G1(-127.95,9.84) G2(-108.27,9.84) G3(-88.58,9.84) G5(-49.21,9.84) G10(49.21,9.84) G12(88.58,9.84) G13(108.27,9.84) G14(127.95,9.84) H1(-127.95,-9.84) H2(-108.27,-9.84) H3(-88.58,-9.84) H5(-49.21,-9.84) H10(49.21,-9.84) H12(88.58,-9.84) H13(108.27,-9.84) H14(127.95,-9.84) J1(-127.95,-29.53) J2(-108.27,-29.53) J3(-88.58,-29.53) J5(-49.21,-29.53) J10(49.21,-29.53) J12(88.58,-29.53) J13(108.27,-29.53) J14(127.95,-29.53) K1(-127.95,-49.21) K2(-108.27,-49.21) K3(-88.58,-49.21) K5(-49.21,-49.21) K6(-29.53,-49.21) K7(-9.84,-49.21) K8(9.84,-49.21) K9(29.53,-49.21) K10(49.21,-49.21) K12(88.58,-49.21) K13(108.27,-49.21) K14(127.95,-49.21) L1(-127.95,-68.9) L2(-108.27,-68.9) L3(-88.58,-68.9) L12(88.58,-68.9) L13(108.27,-68.9) L14(127.95,-68.9) M1(-127.95,-88.58) M2(-108.27,-88.58) M3(-88.58,-88.58) M4(-68.9,-88.58) M5(-49.21,-88.58) M6(-29.53,-88.58) M7(-9.84,-88.58) M8(9.84,-88.58) M9(29.53,-88.58) M10(49.21,-88.58) M11(68.9,-88.58) M12(88.58,-88.58) M13(108.27,-88.58) M14(127.95,-88.58) N1(-127.95,-108.27) N2(-108.27,-108.27) N3(-88.58,-108.27) N4(-68.9,-108.27) N5(-49.21,-108.27) N6(-29.53,-108.27) N7(-9.84,-108.27) N8(9.84,-108.27) N9(29.53,-108.27) N10(49.21,-108.27) N11(68.9,-108.27) N12(88.58,-108.27) N13(108.27,-108.27) N14(127.95,-108.27) P1(-127.95,-127.95) P2(-108.27,-127.95) P3(-88.58,-127.95) P4(-68.9,-127.95) P5(-49.21,-127.95) P6(-29.53,-127.95) P7(-9.84,-127.95) P8(9.84,-127.95) P9(29.53,-127.95) P10(49.21,-127.95) P11(68.9,-127.95) P12(88.58,-127.95) P13(108.27,-127.95) P14(127.95,-127.95)
  silkscreen extent -226,-256 226,256
CONN3-PWR-PJ102A [mil] "CONN3-PWR-PJ102A"
  oval 70x180 hole 40 mask+2: 1(-245,0)
  oval 70x150 hole 40 mask+2: 2(-9,0)
  oval 150x70 hole 40 mask+2: 3(-127,185)
  silkscreen extent -280,-180 295,180
CONN19_HDMI [mm] "CONN19_HDMI"
  rect 0.23x0.85 smd mask+0.051: 1(-1.8,-3.265) 3(-1.4,-3.265) 5(-1,-3.265) 7(-0.6,-3.265) 9(-0.2,-3.265) 11(0.2,-3.265) 13(0.6,-3.265) 15(1,-3.265) 17(1.4,-3.265) 19(1.8,-3.265)
  rect 0.23x1 smd mask+0.051: 2(-1.6,-2.04) 4(-1.2,-2.04) 6(-0.8,-2.04) 8(-0.4,-2.04) 10(0,-2.04) 12(0.4,-2.04) 14(0.8,-2.04) 16(1.2,-2.04) 18(1.6,-2.04)
  oval 1.651x2.54 hole 0.381 mask+0.051: 20(-3.1,1.5) 21(3.1,1.5)
  rect 2.4x1.38 smd mask+0.051: 22(-3.45,-1.86) 23(3.45,-1.86)
  silkscreen extent -3.25,-3.6 3.25,3.9
DCK5_2P15X1P4 [mm] "DCK5_2P15X1P4"
  rect 0.4x0.9 smd mask+0.051: 1(-0.65,-1.1) 2(0,-1.1) 3(0.65,-1.1) 4(0.65,1.1) 5(-0.65,1.1)
  silkscreen extent -1.07,-0.7 1.07,0.7
DGN-16X60 [mil] "DGN-16X60"
  oval 16x60 smd mask+2: 1(38.4,91) 2(12.8,91) 3(-12.8,91) 4(-38.4,91) 5(-38.4,-91) 6(-12.8,-91) 7(12.8,-91) 8(38.4,-91)
  rect 80x80 smd mask+2: 9(0,0)
  BOTTOM region: 75,-75 75,75 -75,75 -75,-75 75,-75
  silkscreen extent -60,-60 60,60
HEADER10X2_SMD [mil] "HEADER10X2_SMD"
  rect 28x110 smd mask+2: 1(225,106.5) 2(225,-106.5) 3(175,106.5) 4(175,-106.5) 5(125,106.5) 6(125,-106.5) 7(75,106.5) 8(75,-106.5) 9(25,106.5) 10(25,-106.5) 11(-25,106.5) 12(-25,-106.5) 13(-75,106.5) 14(-75,-106.5) 15(-125,106.5) 16(-125,-106.5) 17(-175,106.5) 18(-175,-106.5) 19(-225,106.5) 20(-225,-106.5)
  silkscreen extent -250,-150 250,150
HEADER23X2 [mil] "HEADER23X2"
  rect 60x60 hole 30 mask+2: 1(-1100,-50)
  round 60 hole 30 mask+2: 2(-1100,50) 3(-1000,-50) 4(-1000,50) 5(-900,-50) 6(-900,50) 7(-800,-50) 8(-800,50) 9(-700,-50) 10(-700,50) 11(-600,-50) 12(-600,50) 13(-500,-50) 14(-500,50) 15(-400,-50) 16(-400,50) 17(-300,-50) 18(-300,50) 19(-200,-50) 20(-200,50) 21(-100,-50) 22(-100,50) 23(0,-50) 24(0,50) 25(100,-50) 26(100,50) 27(200,-50) 28(200,50) 29(300,-50) 30(300,50) 31(400,-50) 32(400,50) 33(500,-50) 34(500,50) 35(600,-50) 36(600,50) 37(700,-50) 38(700,50) 39(800,-50) 40(800,50) 41(900,-50) 42(900,50) 43(1000,-50) 44(1000,50) 45(1100,-50) 46(1100,50)
  silkscreen extent -1150,-100 1150,100
LED_0603 [mil] "LED_0603"
  rect 30x40 smd mask+2: 1(-32.5,0) 2(32.5,0)
  silkscreen extent -70,-35 60,35
MTGH200C125D_PL [mil] "MTGH200C125D_PL"
  round 175 hole 125 mask+2: 1(-15.5,0)
OSC4_61X65LS_79X98SMD [mil] "OSC4_61X65LS_79X98SMD"
  rect 28x35 smd mask+2: 1(-32.5,-30.5) 2(32.5,-30.5) 3(32.5,30.5) 4(-32.5,30.5)
  silkscreen extent -62,-62 62,62
POLYSW200-5638-310 [mil] "POLYSW200-5638-310"
  round 65 hole 40 mask+2: 1(-100,50) 2(100,-50)
  silkscreen extent -150,-50 150,50
QFN32_5X5MM_EP3P3MM [mil] "QFN32_5X5MM_EP3P3MM"
  oval 10x33 smd mask+2: 1(-68.95,-99) 8(68.95,-99) 17(68.95,99) 24(-68.95,99)
  rect 10x33 smd mask+2: 2(-49.25,-99) 3(-29.55,-99) 4(-9.85,-99) 5(9.85,-99) 6(29.55,-99) 7(49.25,-99) 18(49.25,99) 19(29.55,99) 20(9.85,99) 21(-9.85,99) 22(-29.55,99) 23(-49.25,99)
  oval 33x10 smd mask+2: 9(99,-68.95) 16(99,68.95) 25(-99,68.95) 32(-99,-68.95)
  rect 33x10 smd mask+2: 10(99,-49.25) 11(99,-29.55) 12(99,-9.85) 13(99,9.85) 14(99,29.55) 15(99,49.25) 26(-99,49.25) 27(-99,29.55) 28(-99,9.85) 29(-99,-9.85) 30(-99,-29.55) 31(-99,-49.25)
  rect 134x134 smd mask+2: 33(0,0)
  TOP keep-out region: 76,-105.5 76,-76 105.5,-76 105.5,-105.5 76,-105.5
  TOP keep-out region: -105.5,-76 -105.5,-105.5 -76,-105.5 -76,-76 -105.5,-76
  TOP keep-out region: -76,105.5 -76,76 -105.5,76 -105.5,105.5 -76,105.5
  TOP keep-out region: 76,105.5 76,76 105.5,76 105.5,105.5 76,105.5
  silkscreen extent -112,-138 101,101
QFN64S9X9P5 [mm] "QFN64S9X9P5"
  rect 0.6x0.25 smd mask+0.051: 1(-4.35,3.75) 2(-4.35,3.25) 3(-4.35,2.75) 4(-4.35,2.25) 5(-4.35,1.75) 6(-4.35,1.25) 7(-4.35,0.75) 8(-4.35,0.25) 9(-4.35,-0.25) 10(-4.35,-0.75) 11(-4.35,-1.25) 12(-4.35,-1.75) 13(-4.35,-2.25) 14(-4.35,-2.75) 15(-4.35,-3.25) 16(-4.35,-3.75) 33(4.35,-3.75) 34(4.35,-3.25) 35(4.35,-2.75) 36(4.35,-2.25) 37(4.35,-1.75) 38(4.35,-1.25) 39(4.35,-0.75) 40(4.35,-0.25) 41(4.35,0.25) 42(4.35,0.75) 43(4.35,1.25) 44(4.35,1.75) 45(4.35,2.25) 46(4.35,2.75) 47(4.35,3.25) 48(4.35,3.75)
  rect 0.25x0.6 smd mask+0.051: 17(-3.75,-4.35) 18(-3.25,-4.35) 19(-2.75,-4.35) 20(-2.25,-4.35) 21(-1.75,-4.35) 22(-1.25,-4.35) 23(-0.75,-4.35) 24(-0.25,-4.35) 25(0.25,-4.35) 26(0.75,-4.35) 27(1.25,-4.35) 28(1.75,-4.35) 29(2.25,-4.35) 30(2.75,-4.35) 31(3.25,-4.35) 32(3.75,-4.35) 49(3.75,4.35) 50(3.25,4.35) 51(2.75,4.35) 52(2.25,4.35) 53(1.75,4.35) 54(1.25,4.35) 55(0.75,4.35) 56(0.25,4.35) 57(-0.25,4.35) 58(-0.75,4.35) 59(-1.25,4.35) 60(-1.75,4.35) 61(-2.25,4.35) 62(-2.75,4.35) 63(-3.25,4.35) 64(-3.75,4.35)
  rect 5.08x5.08 smd mask+0.051: 65(0,0)
  silkscreen extent -4.5,-4.5 4.5,4.5
RD205SMD_250D [mil] "RD205SMD_250D"
  rect 120x65 smd mask+2: 1(-102.5,0) 2(102.5,0)
  silkscreen extent -188,-125 125,125
RJ45-7499010211A [mil] "RJ45-7499010211A"
  rect 60x60 hole 40 mask+2: 1(-175,252.5)
  round 60 hole 40 mask+2: 2(-125,352.5) 3(-75,252.5) 4(-25,352.5) 5(25,252.5) 6(75,352.5) 7(125,252.5) 8(175,352.5) 9(-249,-190.5) 10(-149,-130.5) 11(149,-190.5) 12(249,-130.5)
  round 90 hole 63 mask+2: 13(-310,122.5) 14(310,122.5)
  round 40 / inner round 150 / far side round 40 hole 128 mask+2: " "(-225,2.5) " "(225,2.5)
  Multi-Layer keep-out circle w1: c-225,2.5 r81
  Multi-Layer keep-out circle w1: c225,2.5 r81
  silkscreen extent -313,-426 313,435
SD-MICRO-SCHA5B0300 [mil] "SD-MICRO-SCHA5B0300"
  rect 36x18 smd mask+2: 1(285.72,130) 2(285.72,157.56) 3(285.72,185.12) 4(285.72,212.68) 5(-285.72,212.68) 6(-285.72,185.12) 7(-285.72,157.56) 8(-285.72,130)
  rect 20x35 smd mask+2: 9(-148.62,-263.28) 10(235.24,-263.28)
  rect 35x79 smd mask+2: 11(285.43,-170.59) 12(-285.43,-119.41)
  rect 44x60 smd mask+2: 13(283.32,262.48) 14(-283.32,262.48)
  rect 47x43 smd mask+2: 15(134.84,-282.91) 16(-101.37,-282.91)
  silkscreen extent -288,-288 288,315
SIP6 [mil] "SIP6"
  rect 60x60 hole 40 mask+2: 1(0,250)
  round 60 hole 40 mask+2: 2(0,150) 3(0,50) 4(0,-50) 5(0,-150) 6(0,-250)
  silkscreen extent -50,-300 50,300
SM-7351-IND-0805 [mil] "SM-7351-IND-0805"
  rect 55x61 smd mask+2: 1(37.4,0) 2(-37.4,0)
  silkscreen extent -43,-28 43,28
SMINI6-F3-B [mil] "SMINI6-F3-B"
  rect 12x37.4 smd mask+2: 1(25.59,29.53) 2(0,29.53) 3(-25.59,29.53) 4(-25.59,-29.53) 5(0,-29.53) 6(25.59,-29.53)
  silkscreen extent -39,-25 39,25
SO8-25X75 [mil] "SO8-25X75"
  oval 25x75 smd mask+2: 1(75,110) 2(25,110) 3(-25,110) 4(-75,110) 5(-75,-110) 6(-25,-110) 7(25,-110) 8(75,-110)
  silkscreen extent -113,-75 132,125
SOD323 [mil] "SOD323"
  rect 31.5x31.5 smd mask+2: 1(44.29,0) 2(-44.29,0)
  silkscreen extent -65,-35 95,35
SOP8_DCT [mil] "SOP8_DCT"
  rect 12x63 smd mask+2: 1(38.4,67) 2(12.8,67) 3(-12.8,67) 4(-38.4,67) 5(-38.4,-67) 6(-12.8,-67) 7(12.8,-67) 8(38.4,-67)
  silkscreen extent -64,-63 64,63
SOT23-5 [mil] "SOT23-5"
  rect 25x40 smd mask+2: 1(37.5,51) 2(0,51) 3(-37.5,51) 4(-37.5,-51) 5(37.5,-51)
  silkscreen extent -75,-88 75,88
SW4SMD_63X161LS [mil] "SW4SMD_63X161LS"
  rect 35x40 smd mask+2: 1(-80.71,-31.5) 2(-80.71,31.5) 3(80.71,-31.5) 4(80.71,31.5)
  silkscreen extent -108,-59 108,59
TP1-8040 [mil] "TP1-8040"
  round 60 hole 40 mask+2: 1(0,0)
  silkscreen extent -50,-50 50,50
TP60C33D [mil] "TP60C33D"
  round 60 hole 30 mask+2: 1(0,0)
  silkscreen extent -50,-50 50,50
TP60C_SMD [mil] "TP60C_SMD"
  round 50 smd mask+2: 1(0,0)
TSSOP10 [mil] "TSSOP10"
  rect 12x75 smd mask+2: 1(-39.37,-78)
  rect 12x65 smd mask+2: 2(-19.69,-83) 3(0,-83) 4(19.69,-83) 5(39.37,-83) 6(39.37,83) 7(19.69,83) 8(0,83) 9(-19.69,83) 10(-39.37,83)
  silkscreen extent -63,-138 63,138
U_6_DRY [mil] "U_6_DRY"
  rect 12x20 smd mask+2: 1(-19.68,-17.28) 2(0,-17.28) 3(19.68,-17.28) 4(19.68,17.28) 5(0,17.28) 6(-19.68,17.28)
  silkscreen extent -30,-21 30,21
U_8_DCU [mil] "U_8_DCU"
  rect 10x50 smd mask+2: 1(29.5,58) 2(9.8,58) 3(-9.8,58) 4(-29.5,58) 5(-29.5,-58) 6(-9.8,-58) 7(9.8,-58) 8(29.5,-58)
  silkscreen extent -42,-48 42,48
U_48_RSL [mil] "U_48_RSL"
  rect 31.5x7.87 smd mask+2: 1(-121.06,86.61) 2(-121.06,70.87) 3(-121.06,55.12) 4(-121.06,39.37) 5(-121.06,23.62) 6(-121.06,7.87) 7(-121.06,-7.87) 8(-121.06,-23.62) 9(-121.06,-39.37) 10(-121.06,-55.12) 11(-121.06,-70.87) 12(-121.06,-86.61) 25(121.06,-86.61) 26(121.06,-70.87) 27(121.06,-55.12) 28(121.06,-39.37) 29(121.06,-23.62) 30(121.06,-7.87) 31(121.06,7.87) 32(121.06,23.62) 33(121.06,39.37) 34(121.06,55.12) 35(121.06,70.87) 36(121.06,86.61)
  rect 7.87x31.5 smd mask+2: 13(-86.61,-121.06) 14(-70.87,-121.06) 15(-55.12,-121.06) 16(-39.37,-121.06) 17(-23.62,-121.06) 18(-7.87,-121.06) 19(7.87,-121.06) 20(23.62,-121.06) 21(39.37,-121.06) 22(55.12,-121.06) 23(70.87,-121.06) 24(86.61,-121.06) 37(86.61,121.06) 38(70.87,121.06) 39(55.12,121.06) 40(39.37,121.06) 41(23.62,121.06) 42(7.87,121.06) 43(-7.87,121.06) 44(-23.62,121.06) 45(-39.37,121.06) 46(-55.12,121.06) 47(-70.87,121.06) 48(-86.61,121.06)
  rect 159.45x159.45 smd mask+2: 49(-8.86,8.86)
  silkscreen extent -121,-121 121,121
USB5MINI_4SHIELDED_SMD-5 [mm] "USB5MINI_4SHIELDED_SMD-5"
  rect 1.4x0.5 smd mask+0.051: 1(-3,-1.6) 2(-3,-0.8) 3(-3,0) 4(-3,0.8) 5(-3,1.6)
  rect 3.81x2.54 smd mask+0.051: 6(-0.6,-4.2) 7(-0.6,4.2)
  rect 0.8x2.35 smd mask+0.051: 8(2.2,-2.675) 9(2.2,2.675)
  TOP keep-out region: 1.35,-3.9 1.75,-3.9 1.75,-1.45 2.65,-1.45 2.65,-3.9 3.1,-3.9 3.1,3.9 2.65,3.9 2.65,1.45 1.75,1.45 1.75,3.9 1.35,3.9 1.35,2.9 1,2.9 1,1.5 -0.5,1.5 -0.5,-1.5 1,-1.5 1,-2.9 1.35,-2.9 1.35,-3.9
  silkscreen extent -3.4,-3.85 3.6,3.85
USB_A_SH [mil] "USB_A_SH"
  round 65 hole 40 mask+2: 1(-137.1,235.7) 2(-38.7,235.7) 3(40.1,235.7) 4(138.5,235.7)
  oval 80x135 hole 40 mask+2: 5(-258,129) 6(259.4,129)
  silkscreen extent -258,-276 258,276
XTAL4_126-216SMD [mil] "XTAL4_126-216SMD"
  rect 50x75 smd mask+2: 1(-108.2,-63) 2(108.3,-63) 3(108.3,63) 4(-108.2,63)
  silkscreen extent -163,-88 163,88
XTAL150SMD_125X196 [mil] "XTAL150SMD_125X196"
  rect 70x85 smd mask+2: 1(-74.8,0) 2(74.8,0)
  silkscreen extent -118,-69 118,69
